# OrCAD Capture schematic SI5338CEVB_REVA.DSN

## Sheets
1 5338 main: size D; title: Si5338 Customer EVB; rev: A
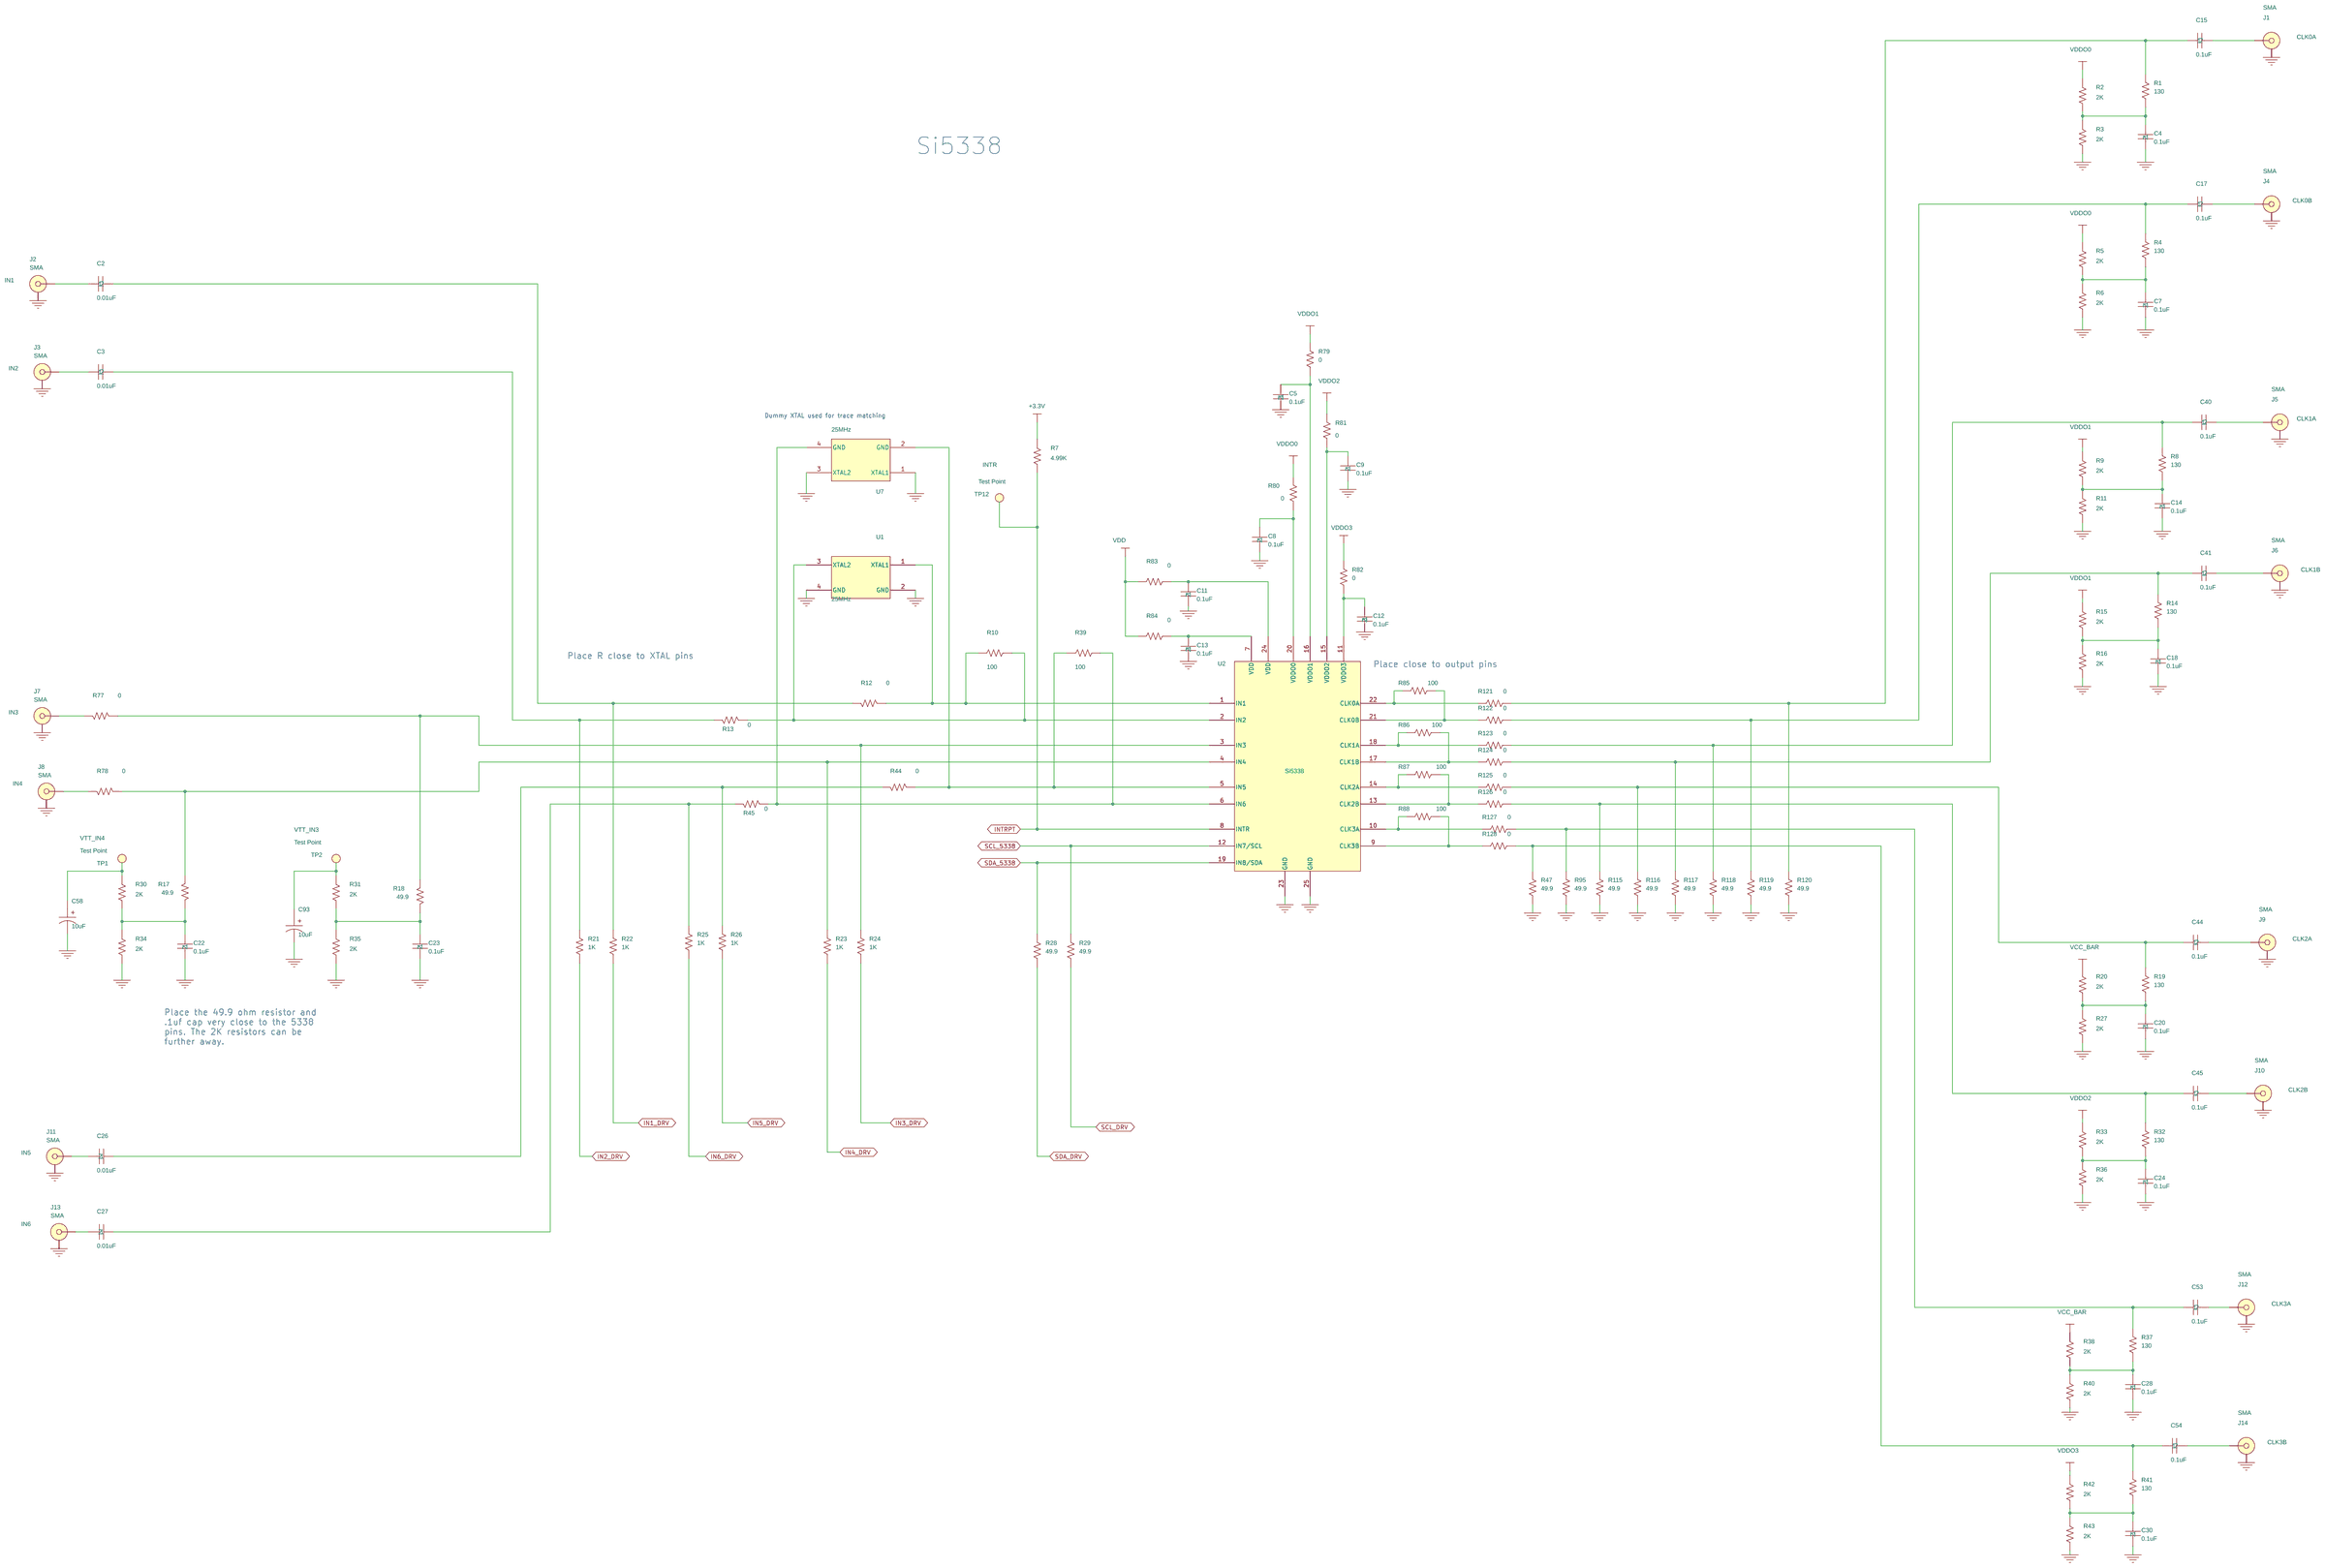
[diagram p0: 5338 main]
2 MCU: size C
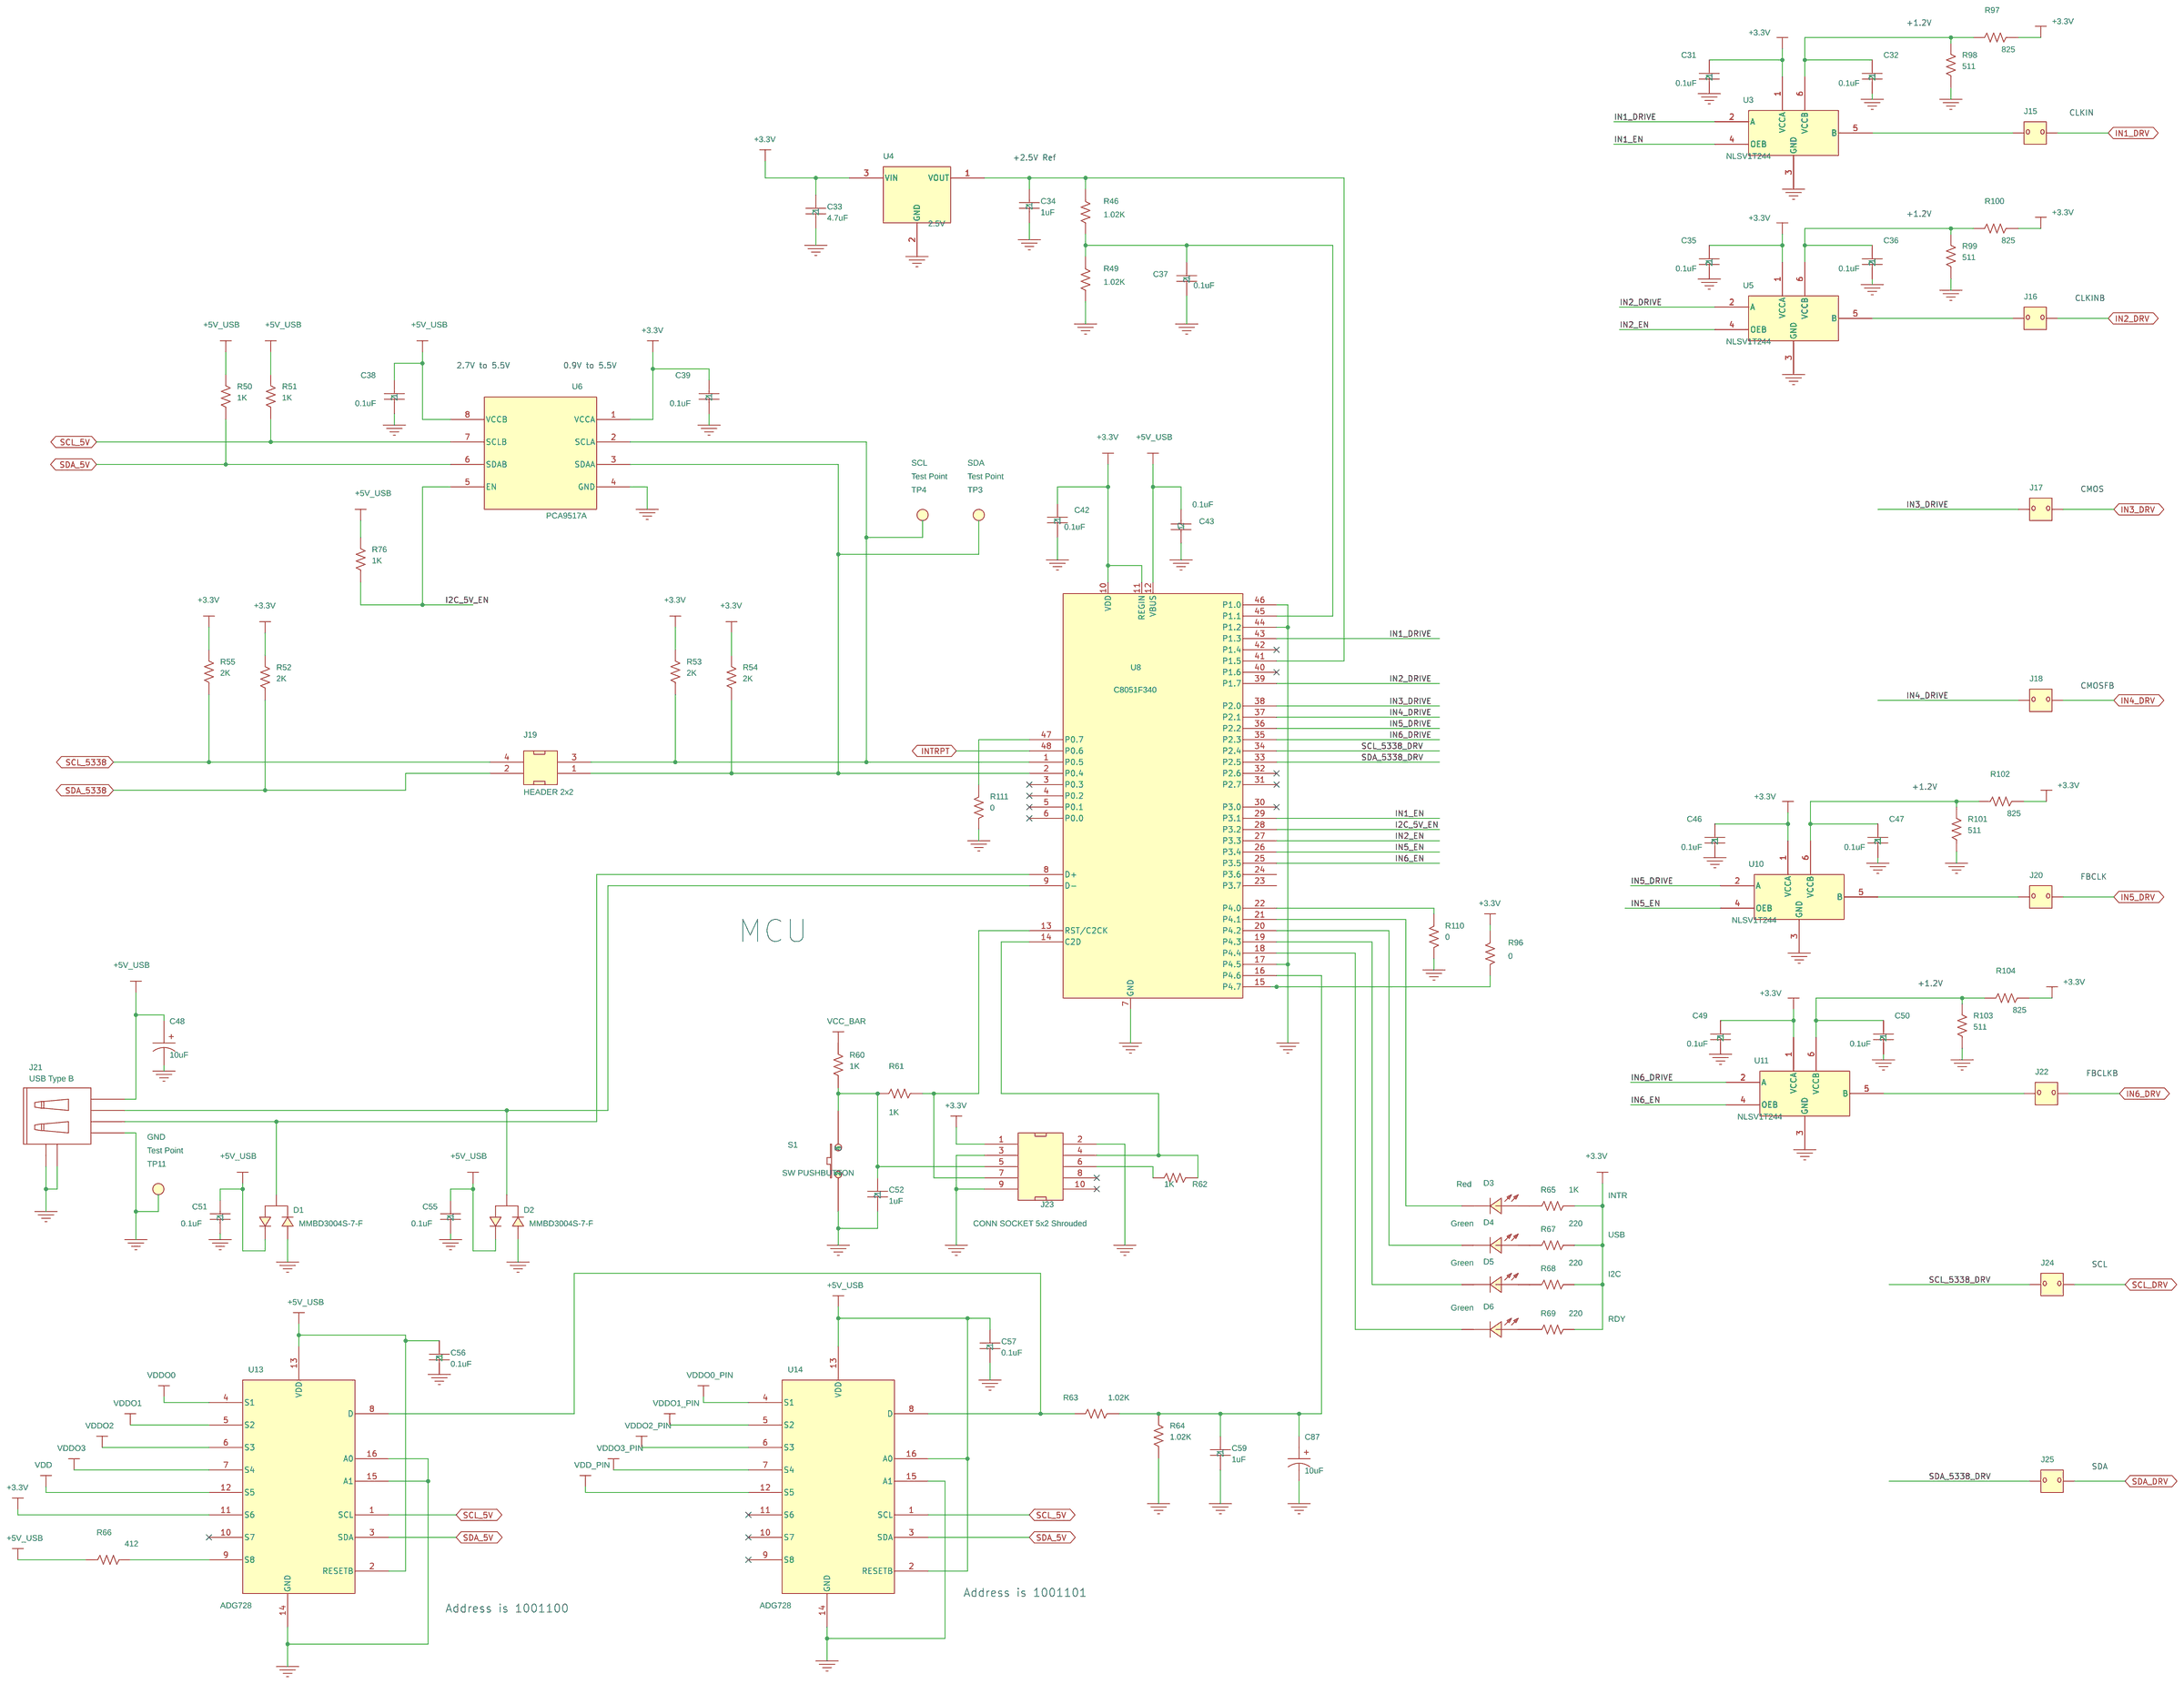
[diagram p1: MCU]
3 Voltage Regulation: size C
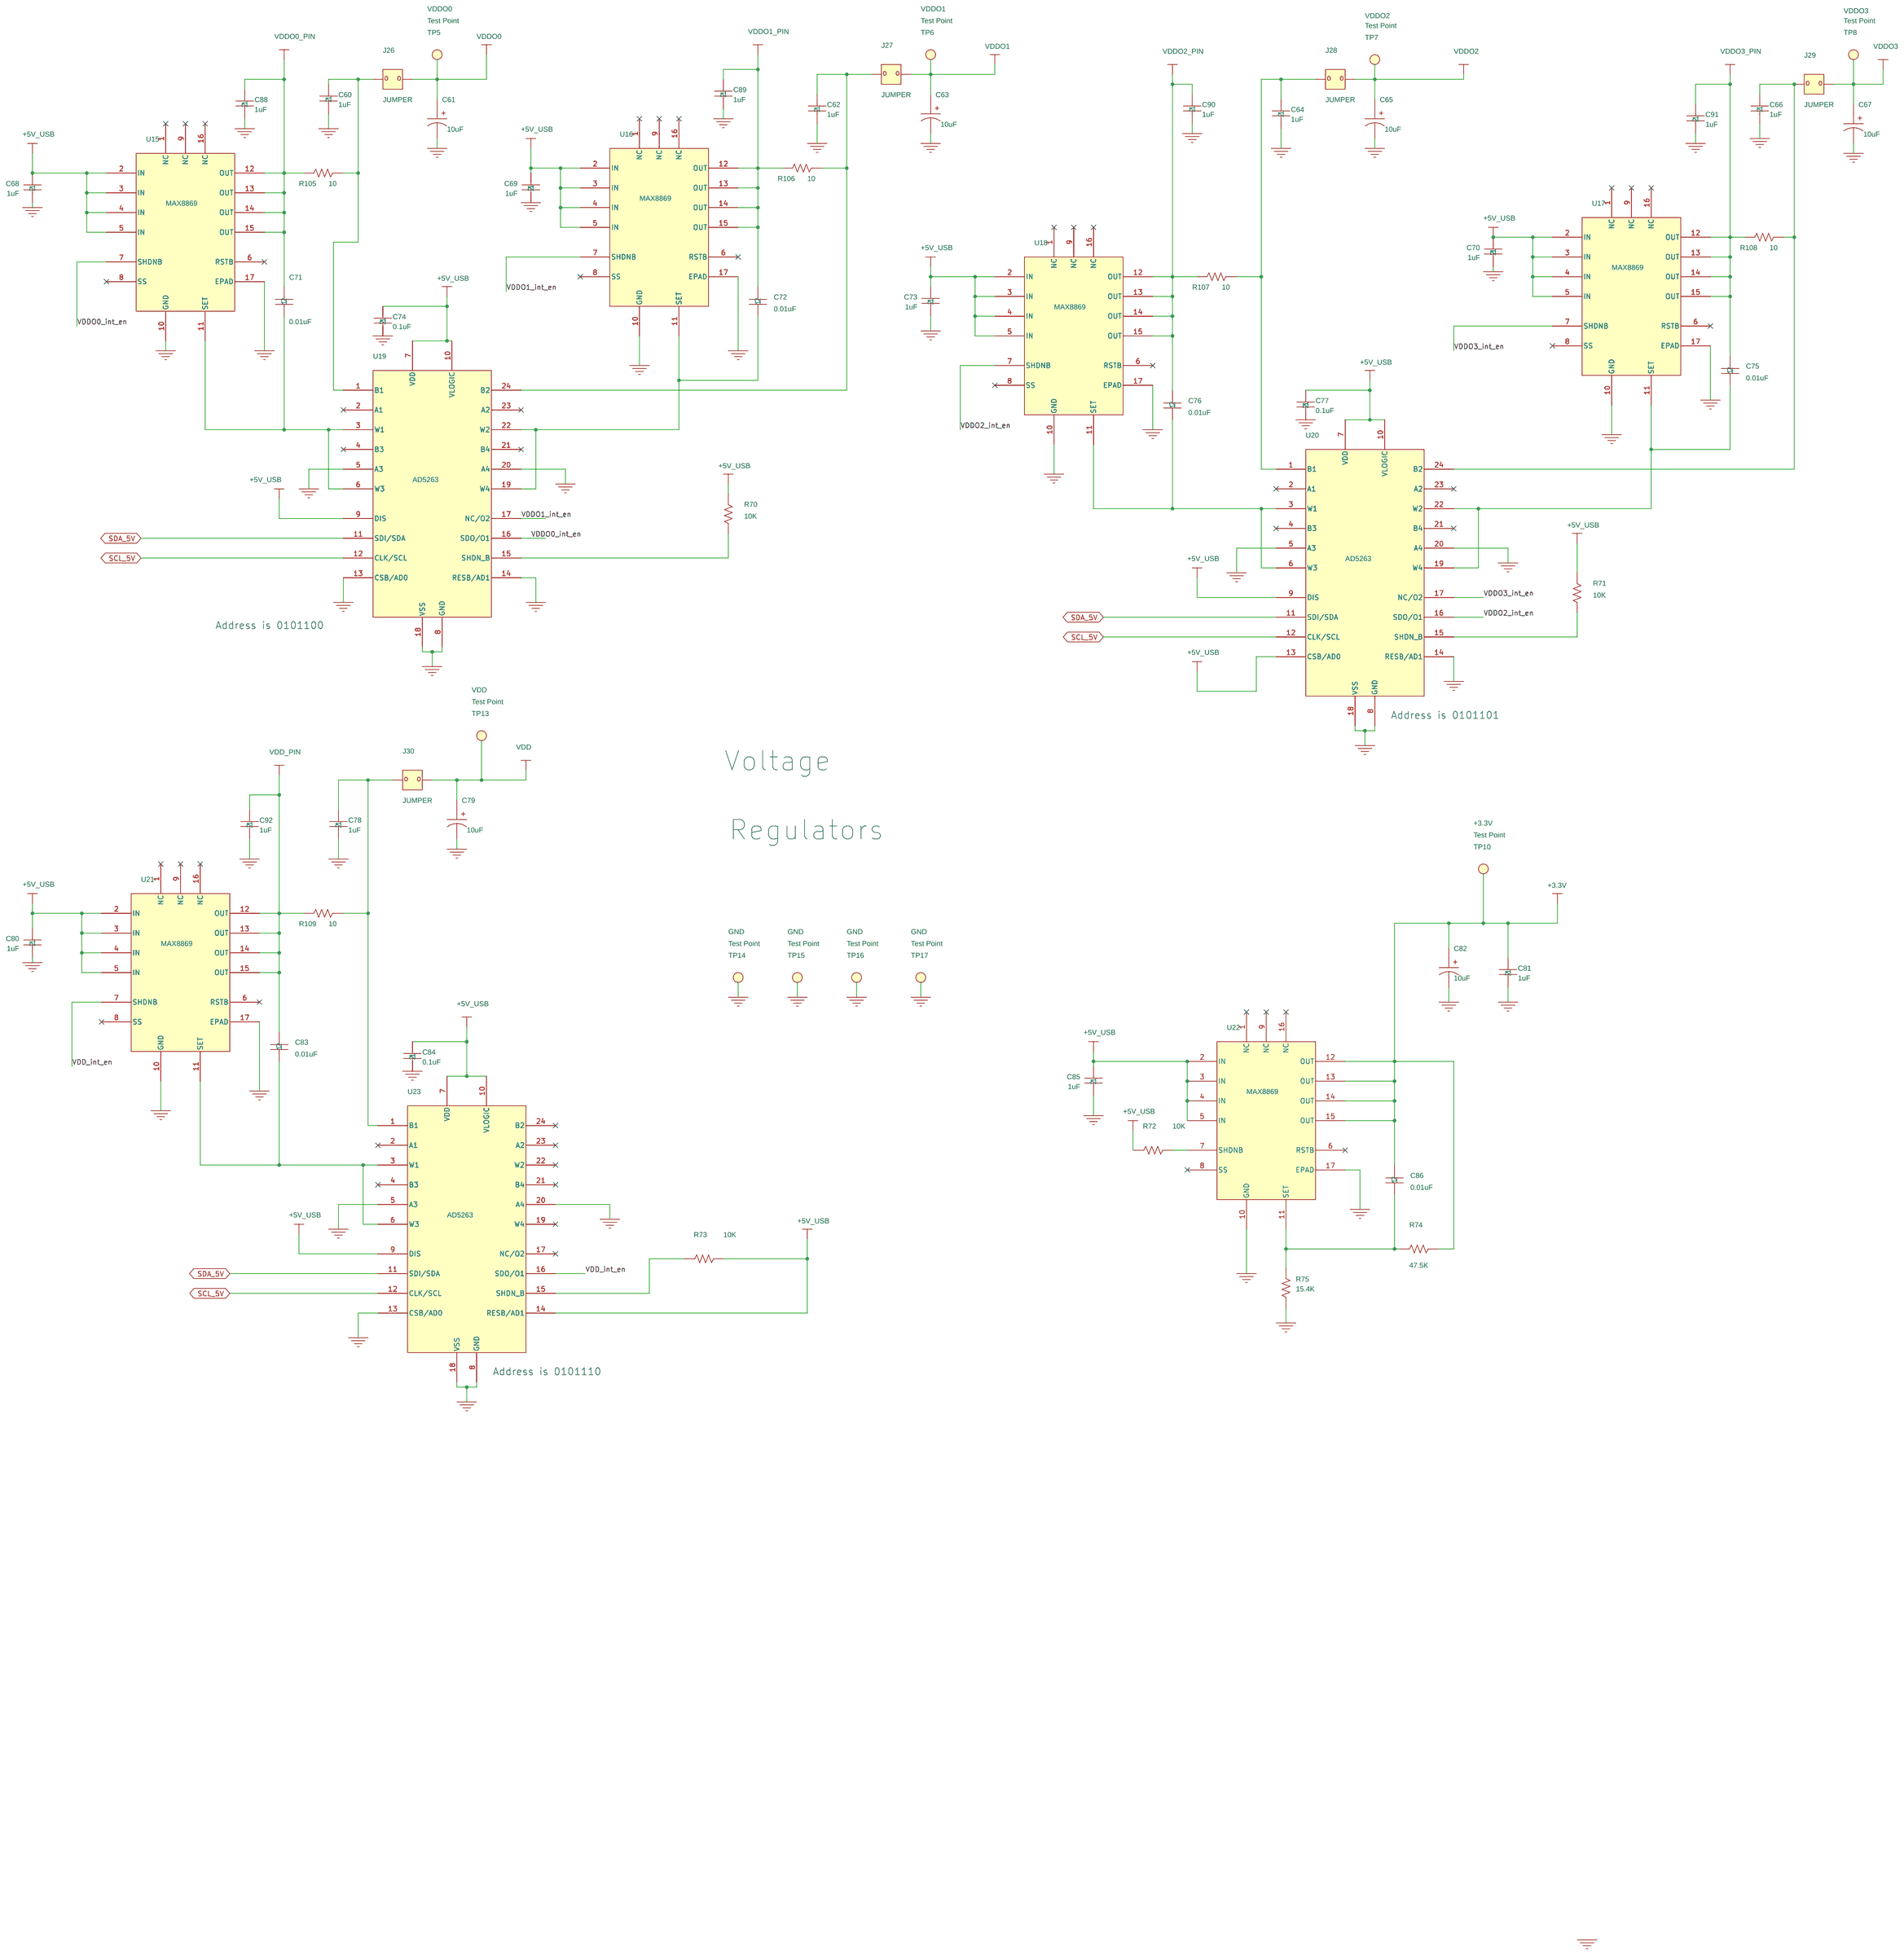
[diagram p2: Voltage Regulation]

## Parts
sheet 5338 main
C2  0.01uF  [C0402]
C3  0.01uF  [C0402]
C4  0.1uF  [C0402]
C5  0.1uF  [C0402L]
C7  0.1uF  [C0402]
C8  0.1uF  [C0402L]
C9  0.1uF  [C0402L]
C11  0.1uF  [C0402L]
C12  0.1uF  [C0402L]
C13  0.1uF  [C0402L]
C14  0.1uF  [C0402]
C15  0.1uF  [C0402]
C17  0.1uF  [C0402]
C18  0.1uF  [C0402]
C20  0.1uF  [C0402]
C22  0.1uF  [C0402L]
C23  0.1uF  [C0402L]
C24  0.1uF  [C0402]
C26  0.01uF  [C0402]
C27  0.01uF  [C0402]
C28  0.1uF  [C0402]
C30  0.1uF  [C0402]
C40  0.1uF  [C0402]
C41  0.1uF  [C0402]
C44  0.1uF  [C0402]
C45  0.1uF  [C0402]
C53  0.1uF  [C0402]
C54  0.1uF  [C0402]
C58  10uF  [6032_EIAC]
C93  10uF  [6032_EIAC]
J1  SMA  [SMA-EDGE-5]
J2  SMA  [SMA-EDGE-5]
J3  SMA  [SMA-EDGE-5]
J4  SMA  [SMA-EDGE-5]
J5  SMA  [SMA-EDGE-5]
J6  SMA  [SMA-EDGE-5]
J7  SMA  [SMA-EDGE-5]
J8  SMA  [SMA-EDGE-5]
J9  SMA  [SMA-EDGE-5]
J10  SMA  [SMA-EDGE-5]
J11  SMA  [SMA-EDGE-5]
J12  SMA  [SMA-EDGE-5]
J13  SMA  [SMA-EDGE-5]
J14  SMA  [SMA-EDGE-5]
R1  130  [R0402]
R2  2K  [R0402]
R3  2K  [R0402]
R4  130  [R0402]
R5  2K  [R0402]
R6  2K  [R0402]
R7  4.99K  [R0402]
R8  130  [R0402]
R9  2K  [R0402]
R10  100  [R0201]
R11  2K  [R0402]
R12  0  [R0402]
R13  0  [R0402]
R14  130  [R0402]
R15  2K  [R0402]
R16  2K  [R0402]
R17  49.9  [R0402L]
R18  49.9  [R0402L]
R19  130  [R0402]
R20  2K  [R0402]
R21  1K  [R0402]
R22  1K  [R0402]
R23  1K  [R0402]
R24  1K  [R0402]
R25  1K  [R0402]
R26  1K  [R0402]
R27  2K  [R0402]
R28  49.9  [R0402]
R29  49.9  [R0402]
R30  2K  [R0402]
R31  2K  [R0402]
R32  130  [R0402]
R33  2K  [R0402]
R34  2K  [R0402]
R35  2K  [R0402]
R36  2K  [R0402]
R37  130  [R0402]
R38  2K  [R0402]
R39  100  [R0201]
R40  2K  [R0402]
R41  130  [R0402]
R42  2K  [R0402]
R43  2K  [R0402]
R44  0  [R0402]
R45  0  [R0402]
R47  49.9  [R0402L]
R77  0  [R0402]
R78  0  [R0402]
R79  0  [R0603]
R80  0  [R0603]
R81  0  [R0603]
R82  0  [R0603]
R83  0  [R0603]
R84  0  [R0603]
R85  100  [R0201]
R86  100  [R0201]
R87  100  [R0201]
R88  100  [R0201]
R95  49.9  [R0402L]
R115  49.9  [R0402L]
R116  49.9  [R0402L]
R117  49.9  [R0402L]
R118  49.9  [R0402L]
R119  49.9  [R0402L]
R120  49.9  [R0402L]
R121  0  [R0201]
R122  0  [R0201]
R123  0  [R0201]
R124  0  [R0201]
R125  0  [R0201]
R126  0  [R0201]
R127  0  [R0201]
R128  0  [R0201]
TP1  Test Point  [TESTPOINT]
TP2  Test Point  [TESTPOINT]
TP12  Test Point  [TESTPOINT]
U1  25MHz  [XTAL4N-MULTI]
U2  Si5338  [QFN24N4X4P0.5]
U7  25MHz  [XTAL4N-MULTI]
sheet MCU
C31  0.1uF  [C0402]
C32  0.1uF  [C0402]
C33  4.7uF  [C1206]
C34  1uF  [C1206]
C35  0.1uF  [C0402]
C36  0.1uF  [C0402]
C37  0.1uF  [C0402]
C38  0.1uF  [C0402]
C39  0.1uF  [C0402]
C42  0.1uF  [C0402]
C43  0.1uF  [C0402]
C46  0.1uF  [C0402]
C47  0.1uF  [C0402]
C48  10uF  [6032_EIAC]
C49  0.1uF  [C0402]
C50  0.1uF  [C0402]
C51  0.1uF  [C0402]
C52  1uF  [C1206]
C55  0.1uF  [C0402]
C56  0.1uF  [C0402]
C57  0.1uF  [C0402]
C59  1uF  [C1206]
C87  10uF  [6032_EIAC]
D1  MMBD3004S-7-F  [SOT23-AKC]
D2  MMBD3004S-7-F  [SOT23-AKC]
D3  Red  [LED-S-GW-KA]
D4  Green  [LED-S-GW-AK]
D5  Green  [LED-S-GW-AK]
D6  Green  [LED-S-GW-AK]
J15  JUMPER  [CONN-1X2]
J16  JUMPER  [CONN-1X2]
J17  JUMPER  [CONN-1X2]
J18  JUMPER  [CONN-1X2]
J19  HEADER 2x2  [CONN2X2]
J20  JUMPER  [CONN-1X2]
J21  USB Type B  [CONN-USB-B]
J22  JUMPER  [CONN-1X2]
J23  CONN SOCKET 5x2 Shrouded  [CONN2X5-4W]
J24  JUMPER  [CONN-1X2]
J25  JUMPER  [CONN-1X2]
R46  1.02K  [R0402]
R49  1.02K  [R0402]
R50  1K  [R0402]
R51  1K  [R0402]
R52  2K  [R0402]
R53  2K  [R0402]
R54  2K  [R0402]
R55  2K  [R0402]
R60  1K  [R0402]
R61  1K  [R0402]
R62  1K  [R0402]
R63  1.02K  [R0402]
R64  1.02K  [R0402]
R65  1K  [R0402]
R66  412  [R0402]
R67  220  [R0402]
R68  220  [R0402]
R69  220  [R0402]
R76  1K  [R0402]
R96  0  [R0402]
R97  825  [R0603]
R98  511  [R0603]
R99  511  [R0603]
R100  825  [R0603]
R101  511  [R0603]
R102  825  [R0603]
R103  511  [R0603]
R104  825  [R0603]
R110  0  [R0402]
R111  0  [R0402]
S1  SW PUSHBUTTON  [SW-PB-MOM]
TP3  Test Point  [TESTPOINT]
TP4  Test Point  [TESTPOINT]
TP11  Test Point  [TESTPOINT]
U3  NLSV1T244  [UDFN6N1P0.4]
U4  2.5V  [SOT-23]
U5  NLSV1T244  [UDFN6N1P0.4]
U6  PCA9517A  [SO8N6.0P1.27]
U8  C8051F340  [TQFP48N9X9P0.5]
U10  NLSV1T244  [UDFN6N1P0.4]
U11  NLSV1T244  [UDFN6N1P0.4]
U13  ADG728  [TSSOP16N6.4P0.65]
U14  ADG728  [TSSOP16N6.4P0.65]
sheet Voltage Regulation
C60  1uF  [C0603]
C61  10uF  [6032_EIAC]
C62  1uF  [C0603]
C63  10uF  [6032_EIAC]
C64  1uF  [C0603]
C65  10uF  [6032_EIAC]
C66  1uF  [C0603]
C67  10uF  [6032_EIAC]
C68  1uF  [C0603]
C69  1uF  [C0603]
C70  1uF  [C0603]
C71  0.01uF  [C0402]
C72  0.01uF  [C0402]
C73  1uF  [C0603]
C74  0.1uF  [C0402]
C75  0.01uF  [C0402]
C76  0.01uF  [C0402]
C77  0.1uF  [C0402]
C78  1uF  [C0603]
C79  10uF  [6032_EIAC]
C80  1uF  [C0603]
C81  1uF  [C0603]
C82  10uF  [6032_EIAC]
C83  0.01uF  [C0402]
C84  0.1uF  [C0402]
C85  1uF  [C0603]
C86  0.01uF  [C0402]
C88  1uF  [C0603]
C89  1uF  [C0603]
C90  1uF  [C0603]
C91  1uF  [C0603]
C92  1uF  [C0603]
J26  JUMPER  [CONN-1X2]
J27  JUMPER  [CONN-1X2]
J28  JUMPER  [CONN-1X2]
J29  JUMPER  [CONN-1X2]
J30  JUMPER  [CONN-1X2]
R70  10K  [R0402]
R71  10K  [R0402]
R72  10K  [R0402]
R73  10K  [R0402]
R74  47.5K  [R0603]
R75  15.4K  [R0603]
R105  10  [R2512]
R106  10  [R2512]
R107  10  [R2512]
R108  10  [R2512]
R109  10  [R2512]
TP5  Test Point  [TESTPOINT]
TP6  Test Point  [TESTPOINT]
TP7  Test Point  [TESTPOINT]
TP8  Test Point  [TESTPOINT]
TP10  Test Point  [TESTPOINT]
TP13  Test Point  [TESTPOINT]
TP14  Test Point  [TESTPOINT]
TP15  Test Point  [TESTPOINT]
TP16  Test Point  [TESTPOINT]
TP17  Test Point  [TESTPOINT]
U15  MAX8869  [TSSOP16N6.5P0.65E]
U16  MAX8869  [TSSOP16N6.5P0.65E]
U17  MAX8869  [TSSOP16N6.5P0.65E]
U18  MAX8869  [TSSOP16N6.5P0.65E]
U19  AD5263  [TSSOP24N6.4P0.65]
U20  AD5263  [TSSOP24N6.4P0.65]
U21  MAX8869  [TSSOP16N6.5P0.65E]
U22  MAX8869  [TSSOP16N6.5P0.65E]
U23  AD5263  [TSSOP24N6.4P0.65]

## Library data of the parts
C2 = CAP_NP_27: CAP, 0.01uF, 10V, ±20%, X7R, 0402; Manufacturer: Venkel; ManufacturerPN: C0402X7R100-103M; Part_Type: CAP/NP; SiLabsPN: C0402X7R100-103M; Tolerance: ±20%; Type: X7R; Voltage: 10V; Datasheet: PID_C.pdf
C3 C71 = CAP_NP_18: CAP, 0.01uF, 10V, ±20%, X7R, 0402; Manufacturer: Venkel; ManufacturerPN: C0402X7R100-103M; Part_Type: CAP/NP; SiLabsPN: C0402X7R100-103M; Tolerance: ±20%; Type: X7R; Voltage: 10V; Datasheet: PID_C.pdf
C4 C50 = CAP_NP_5: CAP, 0.1uF, 10V, ±10%, X7R, 0402; Manufacturer: Venkel; ManufacturerPN: C0402X7R100-104K; Part_Type: CAP/NP; SiLabsPN: C0402X7R100-104K; Tolerance: ±10%; Type: X7R; Voltage: 10V; Datasheet: PID_C.pdf
C5 = CAP_NP_7: CAP, 0.1uF, 10V, ±10%, X7R, 0402; Manufacturer: Venkel; ManufacturerPN: C0402X7R100-104K; Part_Type: CAP/NP; SiLabsPN: C0402X7R100-104K; Tolerance: ±10%; Type: X7R; Voltage: 10V; Datasheet: PID_C.pdf
C7 C42 = CAP_NP_3: CAP, 0.1uF, 10V, ±10%, X7R, 0402; Manufacturer: Venkel; ManufacturerPN: C0402X7R100-104K; Part_Type: CAP/NP; SiLabsPN: C0402X7R100-104K; Tolerance: ±10%; Type: X7R; Voltage: 10V; Datasheet: PID_C.pdf
C8 C47 C84 = CAP_NP: CAP, 0.1uF, 10V, ±10%, X7R, 0402; Manufacturer: Venkel; ManufacturerPN: C0402X7R100-104K; Part_Type: CAP/NP; SiLabsPN: C0402X7R100-104K; Tolerance: ±10%; Type: X7R; Voltage: 10V; Datasheet: PID_C.pdf
C9 C56 = CAP_NP_9: CAP, 0.1uF, 10V, ±10%, X7R, 0402; Manufacturer: Venkel; ManufacturerPN: C0402X7R100-104K; Part_Type: CAP/NP; SiLabsPN: C0402X7R100-104K; Tolerance: ±10%; Type: X7R; Voltage: 10V; Datasheet: PID_C.pdf
C11 C57 = CAP_NP_14: CAP, 0.1uF, 10V, ±10%, X7R, 0402; Manufacturer: Venkel; ManufacturerPN: C0402X7R100-104K; Part_Type: CAP/NP; SiLabsPN: C0402X7R100-104K; Tolerance: ±10%; Type: X7R; Voltage: 10V; Datasheet: PID_C.pdf
C12 C37 = CAP_NP_13: CAP, 0.1uF, 10V, ±10%, X7R, 0402; Manufacturer: Venkel; ManufacturerPN: C0402X7R100-104K; Part_Type: CAP/NP; SiLabsPN: C0402X7R100-104K; Tolerance: ±10%; Type: X7R; Voltage: 10V; Datasheet: PID_C.pdf
C13 C39 = CAP_NP_20: CAP, 0.1uF, 10V, ±10%, X7R, 0402; Manufacturer: Venkel; ManufacturerPN: C0402X7R100-104K; Part_Type: CAP/NP; SiLabsPN: C0402X7R100-104K; Tolerance: ±10%; Type: X7R; Voltage: 10V; Datasheet: PID_C.pdf
C14 = CAP_NP_11: CAP, 0.1uF, 10V, ±10%, X7R, 0402; Manufacturer: Venkel; ManufacturerPN: C0402X7R100-104K; Part_Type: CAP/NP; SiLabsPN: C0402X7R100-104K; Tolerance: ±10%; Type: X7R; Voltage: 10V; Datasheet: PID_C.pdf
C15 C43 = CAP_NP_4: CAP, 0.1uF, 10V, ±10%, X7R, 0402; Manufacturer: Venkel; ManufacturerPN: C0402X7R100-104K; Part_Type: CAP/NP; SiLabsPN: C0402X7R100-104K; Tolerance: ±10%; Type: X7R; Voltage: 10V; Datasheet: PID_C.pdf
C17 C74 = CAP_NP_22: CAP, 0.1uF, 10V, ±10%, X7R, 0402; Manufacturer: Venkel; ManufacturerPN: C0402X7R100-104K; Part_Type: CAP/NP; SiLabsPN: C0402X7R100-104K; Tolerance: ±10%; Type: X7R; Voltage: 10V; Datasheet: PID_C.pdf
C18 C38 = CAP_NP_8: CAP, 0.1uF, 10V, ±10%, X7R, 0402; Manufacturer: Venkel; ManufacturerPN: C0402X7R100-104K; Part_Type: CAP/NP; SiLabsPN: C0402X7R100-104K; Tolerance: ±10%; Type: X7R; Voltage: 10V; Datasheet: PID_C.pdf
C20 = CAP_NP_25: CAP, 0.1uF, 10V, ±10%, X7R, 0402; Manufacturer: Venkel; ManufacturerPN: C0402X7R100-104K; Part_Type: CAP/NP; SiLabsPN: C0402X7R100-104K; Tolerance: ±10%; Type: X7R; Voltage: 10V; Datasheet: PID_C.pdf
C22 C49 = CAP_NP_2: CAP, 0.1uF, 10V, ±10%, X7R, 0402; Manufacturer: Venkel; ManufacturerPN: C0402X7R100-104K; Part_Type: CAP/NP; SiLabsPN: C0402X7R100-104K; Tolerance: ±10%; Type: X7R; Voltage: 10V; Datasheet: PID_C.pdf
C23 = CAP_NP_26: CAP, 0.1uF, 10V, ±10%, X7R, 0402; Manufacturer: Venkel; ManufacturerPN: C0402X7R100-104K; Part_Type: CAP/NP; SiLabsPN: C0402X7R100-104K; Tolerance: ±10%; Type: X7R; Voltage: 10V; Datasheet: PID_C.pdf
C24 = CAP_NP_19: CAP, 0.1uF, 10V, ±10%, X7R, 0402; Manufacturer: Venkel; ManufacturerPN: C0402X7R100-104K; Part_Type: CAP/NP; SiLabsPN: C0402X7R100-104K; Tolerance: ±10%; Type: X7R; Voltage: 10V; Datasheet: PID_C.pdf
C26 C76 = CAP_NP_21: CAP, 0.01uF, 10V, ±20%, X7R, 0402; Manufacturer: Venkel; ManufacturerPN: C0402X7R100-103M; Part_Type: CAP/NP; SiLabsPN: C0402X7R100-103M; Tolerance: ±20%; Type: X7R; Voltage: 10V; Datasheet: PID_C.pdf
C27 = CAP_NP_24: CAP, 0.01uF, 10V, ±20%, X7R, 0402; Manufacturer: Venkel; ManufacturerPN: C0402X7R100-103M; Part_Type: CAP/NP; SiLabsPN: C0402X7R100-103M; Tolerance: ±20%; Type: X7R; Voltage: 10V; Datasheet: PID_C.pdf
C28 C31 = CAP_NP_15: CAP, 0.1uF, 10V, ±10%, X7R, 0402; Manufacturer: Venkel; ManufacturerPN: C0402X7R100-104K; Part_Type: CAP/NP; SiLabsPN: C0402X7R100-104K; Tolerance: ±10%; Type: X7R; Voltage: 10V; Datasheet: PID_C.pdf
C30 C55 = CAP_NP_6: CAP, 0.1uF, 10V, ±10%, X7R, 0402; Manufacturer: Venkel; ManufacturerPN: C0402X7R100-104K; Part_Type: CAP/NP; SiLabsPN: C0402X7R100-104K; Tolerance: ±10%; Type: X7R; Voltage: 10V; Datasheet: PID_C.pdf
C32 C40 = CAP_NP_16: CAP, 0.1uF, 10V, ±10%, X7R, 0402; Manufacturer: Venkel; ManufacturerPN: C0402X7R100-104K; Part_Type: CAP/NP; SiLabsPN: C0402X7R100-104K; Tolerance: ±10%; Type: X7R; Voltage: 10V; Datasheet: PID_C.pdf
C35 C41 = CAP_NP_10: CAP, 0.1uF, 10V, ±10%, X7R, 0402; Manufacturer: Venkel; ManufacturerPN: C0402X7R100-104K; Part_Type: CAP/NP; SiLabsPN: C0402X7R100-104K; Tolerance: ±10%; Type: X7R; Voltage: 10V; Datasheet: PID_C.pdf
C44 C51 = CAP_NP_1: CAP, 0.1uF, 10V, ±10%, X7R, 0402; Manufacturer: Venkel; ManufacturerPN: C0402X7R100-104K; Part_Type: CAP/NP; SiLabsPN: C0402X7R100-104K; Tolerance: ±10%; Type: X7R; Voltage: 10V; Datasheet: PID_C.pdf
C45 = CAP_NP_23: CAP, 0.1uF, 10V, ±10%, X7R, 0402; Manufacturer: Venkel; ManufacturerPN: C0402X7R100-104K; Part_Type: CAP/NP; SiLabsPN: C0402X7R100-104K; Tolerance: ±10%; Type: X7R; Voltage: 10V; Datasheet: PID_C.pdf
C36 C53 = CAP_NP_17: CAP, 0.1uF, 10V, ±10%, X7R, 0402; Manufacturer: Venkel; ManufacturerPN: C0402X7R100-104K; Part_Type: CAP/NP; SiLabsPN: C0402X7R100-104K; Tolerance: ±10%; Type: X7R; Voltage: 10V; Datasheet: PID_C.pdf
C54 = CAP_NP_12: CAP, 0.1uF, 10V, ±10%, X7R, 0402; Manufacturer: Venkel; ManufacturerPN: C0402X7R100-104K; Part_Type: CAP/NP; SiLabsPN: C0402X7R100-104K; Tolerance: ±10%; Type: X7R; Voltage: 10V; Datasheet: PID_C.pdf
C48 C58 C61 C63 C65 C67 C79 C82 C87 C93 = CAP_POL: CAP, 10uF, 25V, ±20%, TANT, 6032-28; Manufacturer: Kemet; ManufacturerPN: B45196H5106M309; Part_Type: CAP/POL; SiLabsPN: B45196H5106M309; Tolerance: ±20%; Type: TANT; Voltage: 25V; Datasheet: B45196E_High_Cap.pdf
J1 = COAX_5PIN: SMA, 50 Ohm, End Launch Jack Receptacle - Round Contact, Edge Mount; Manufacturer: Johnson Components; ManufacturerPN: 142-0701-801; Part_Type: CON; SiLabsPN: 142-0701-801; Silk: CLK0A; Type: RF; Datasheet: 1420701801.pdf
J2 = COAX_5PIN: SMA, 50 Ohm, End Launch Jack Receptacle - Round Contact, Edge Mount; Manufacturer: Johnson Components; ManufacturerPN: 142-0701-801; Part_Type: CON; SiLabsPN: 142-0701-801; Silk: IN1; Type: RF; Datasheet: 1420701801.pdf
J3 = COAX_5PIN: SMA, 50 Ohm, End Launch Jack Receptacle - Round Contact, Edge Mount; Manufacturer: Johnson Components; ManufacturerPN: 142-0701-801; Part_Type: CON; SiLabsPN: 142-0701-801; Silk: IN2; Type: RF; Datasheet: 1420701801.pdf
J4 = COAX_5PIN: SMA, 50 Ohm, End Launch Jack Receptacle - Round Contact, Edge Mount; Manufacturer: Johnson Components; ManufacturerPN: 142-0701-801; Part_Type: CON; SiLabsPN: 142-0701-801; Silk: CLK0B; Type: RF; Datasheet: 1420701801.pdf
J5 = COAX_5PIN: SMA, 50 Ohm, End Launch Jack Receptacle - Round Contact, Edge Mount; Manufacturer: Johnson Components; ManufacturerPN: 142-0701-801; Part_Type: CON; SiLabsPN: 142-0701-801; Silk: CLK1A; Type: RF; Datasheet: 1420701801.pdf
J6 = COAX_5PIN: SMA, 50 Ohm, End Launch Jack Receptacle - Round Contact, Edge Mount; Manufacturer: Johnson Components; ManufacturerPN: 142-0701-801; Part_Type: CON; SiLabsPN: 142-0701-801; Silk: CLK1B; Type: RF; Datasheet: 1420701801.pdf
J7 = COAX_5PIN: SMA, 50 Ohm, End Launch Jack Receptacle - Round Contact, Edge Mount; Manufacturer: Johnson Components; ManufacturerPN: 142-0701-801; Part_Type: CON; SiLabsPN: 142-0701-801; Silk: IN3; Type: RF; Datasheet: 1420701801.pdf
J8 = COAX_5PIN: SMA, 50 Ohm, End Launch Jack Receptacle - Round Contact, Edge Mount; Manufacturer: Johnson Components; ManufacturerPN: 142-0701-801; Part_Type: CON; SiLabsPN: 142-0701-801; Silk: IN4; Type: RF; Datasheet: 1420701801.pdf
J9 = COAX_5PIN: SMA, 50 Ohm, End Launch Jack Receptacle - Round Contact, Edge Mount; Manufacturer: Johnson Components; ManufacturerPN: 142-0701-801; Part_Type: CON; SiLabsPN: 142-0701-801; Silk: CLK2A; Type: RF; Datasheet: 1420701801.pdf
J10 = COAX_5PIN: SMA, 50 Ohm, End Launch Jack Receptacle - Round Contact, Edge Mount; Manufacturer: Johnson Components; ManufacturerPN: 142-0701-801; Part_Type: CON; SiLabsPN: 142-0701-801; Silk: CLK2B; Type: RF; Datasheet: 1420701801.pdf
J11 = COAX_5PIN: SMA, 50 Ohm, End Launch Jack Receptacle - Round Contact, Edge Mount; Manufacturer: Johnson Components; ManufacturerPN: 142-0701-801; Part_Type: CON; SiLabsPN: 142-0701-801; Silk: IN5; Type: RF; Datasheet: 1420701801.pdf
J12 = COAX_5PIN: SMA, 50 Ohm, End Launch Jack Receptacle - Round Contact, Edge Mount; Manufacturer: Johnson Components; ManufacturerPN: 142-0701-801; Part_Type: CON; SiLabsPN: 142-0701-801; Silk: CLK3A; Type: RF; Datasheet: 1420701801.pdf
J13 = COAX_5PIN: SMA, 50 Ohm, End Launch Jack Receptacle - Round Contact, Edge Mount; Manufacturer: Johnson Components; ManufacturerPN: 142-0701-801; Part_Type: CON; SiLabsPN: 142-0701-801; Silk: IN6; Type: RF; Datasheet: 1420701801.pdf
J14 = COAX_5PIN: SMA, 50 Ohm, End Launch Jack Receptacle - Round Contact, Edge Mount; Manufacturer: Johnson Components; ManufacturerPN: 142-0701-801; Part_Type: CON; SiLabsPN: 142-0701-801; Silk: CLK3B; Type: RF; Datasheet: 1420701801.pdf
R1 R4 R8 R14 R19 R32 R37 R41 = RES_V: RES, 130 Ohm, 1/16W, ±5%, ThickFilm, 0402; Manufacturer: Venkel; ManufacturerPN: CR0402-16W-131F; Part_Type: RES/SMT; Rating: 1/16W; SiLabsPN: CR0402-16W-131F; Tolerance: ±1%; Type: ThickFilm; Datasheet: PID_CR.pdf
R2 R3 R5 R6 R9 R11 R15 R16 R20 R27 R30 R31 R33-R36 R38 R40 R42 R43 = RES_V: RES, 2K, 1/16W, ±25PPM, ±0.1%, ThinFilm, 0402; Manufacturer: Venkel; ManufacturerPN: TFCR0402-16W-E-2001B; Part_Type: RES/SMT; Rating: 1/16W; SiLabsPN: TFCR0402-16W-E-2001B; Tolerance: ±0.1%; Type: ThinFilm; Datasheet: PID_TFCR.pdf
R7 = RES_V: RES, 4.99K, 1/16W, ±1%, ThickFilm, 0402; Manufacturer: Venkel; ManufacturerPN: CR0402-16W-4991F; Part_Type: RES/SMT; Rating: 1/16W; SiLabsPN: CR0402-16W-4991F; Tolerance: ±1%; Type: ThickFilm; Datasheet: PID_CR.pdf
R10 R39 R85-R88 = RES_V: RES, 100 Ohm, 1/20W, ±1%, ThickFilm, 0201; Manufacturer: Venkel; ManufacturerPN: CR0201-20W-1000F; Part_Type: RES/SMT; Rating: 1/20W; SiLabsPN: CR0201-20W-1000F; Tolerance: ±1%; Type: ThickFilm; Datasheet: PID_CR.pdf
R12 R13 R44 R45 R77 R78 R96 R110 R111 = RES_V: RES, 0 Ohm, 1A, ThickFilm, 0402; Manufacturer: Venkel; ManufacturerPN: CR0402-16W-000; Part_Type: RES/SMT; Rating: 1A; SiLabsPN: CR0402-16W-000; Type: ThickFilm; Datasheet: PID_CR.pdf
R17 R18 R28 R29 R47 R95 R115-R120 = RES_V: RES, 49.9 Ohm, 1/16W, ±1%, ThickFilm, 0402; Manufacturer: Venkel; ManufacturerPN: CR0402-16W-49R9F; Part_Type: RES/SMT; Rating: 1/16W; SiLabsPN: CR0402-16W-49R9F; Tolerance: ±1%; Type: ThickFilm; Datasheet: PID_CR.pdf
R21-R26 R50 R51 R60-R62 R65 R76 = RES_V: RES, 1K, 1/16W, ±5%, ThickFilm, 0402; Manufacturer: Venkel; ManufacturerPN: CR0402-16W-102J; Part_Type: RES/SMT; Rating: 1/16W; SiLabsPN: CR0402-16W-102J; Tolerance: ±5%; Type: ThickFilm; Datasheet: PID_CR.pdf
R79-R84 = RES_V: RES, 0 Ohm, 1A, ThickFilm, 0603; Manufacturer: Venkel; ManufacturerPN: CR0603-16W-000; Part_Type: RES/SMT; Rating: 1A; SiLabsPN: CR0603-16W-000; Type: ThickFilm; Datasheet: PID_CR.pdf
R121-R128 = RES_V: RES, 0 Ohm, 1/20W, ±1%, ThickFilm, 0201; Manufacturer: Venkel; ManufacturerPN: CR0201-20W-000F; Part_Type: RES/SMT; Rating: 1/20W; SiLabsPN: TMP-600; Tolerance: ±1%; Type: ThickFilm; Datasheet: PID_CR.pdf
TP1 = TEST_POINT: TH Red TESTPOINT; Manufacturer: Kobiconn; ManufacturerPN: 151-207; SiLabsPN: 151-207; Silk: VTT_IN4; Type: Red
TP2 = TEST_POINT: TH Red TESTPOINT; Manufacturer: Kobiconn; ManufacturerPN: 151-207; SiLabsPN: 151-207; Silk: VTT_IN3; Type: Red
TP12 = TEST_POINT: TH Red TESTPOINT; Manufacturer: Kobiconn; ManufacturerPN: 151-207; SiLabsPN: 151-207; Silk: INTR; Type: Red
U1 U7 = FA-238: XTAL 25MHz, 3.2MM X 2.5MM, LOW PROFILE SMD; Manufacturer: Epson; ManufacturerPN: FA-238 25.0000MB; Part_Type: IC; SiLabsPN: FA-238 25.0000MB; Datasheet: FA-238.pdf
U2 = Si5338: Programmable Four Frequency Clock Multiplier; Manufacturer: SiLabs; Part_Type: IC/SILABS; Type: Timing
C33 = CAP_NP_19: CAP, 4.7uF, 10V, ±20%, X7R, 1206; Manufacturer: Venkel; ManufacturerPN: C1206X7R100-475M; Part_Type: CAP/NP; SiLabsPN: C1206X7R100-475M; Tolerance: ±20%; Type: X7R; Voltage: 10V; Datasheet: PID_C.pdf
C34 = CAP_NP_7: CAP, 1uF, 25V, ±10%, X7R, 1206; Manufacturer: Venkel; ManufacturerPN: C1206X7R250-105K; Part_Type: CAP/NP; SiLabsPN: C1206X7R250-105K; Tolerance: ±10%; Type: X7R; Voltage: 25V; Datasheet: PID_C.pdf
C46 = CAP_NP_18: CAP, 0.1uF, 10V, ±10%, X7R, 0402; Manufacturer: Venkel; ManufacturerPN: C0402X7R100-104K; Part_Type: CAP/NP; SiLabsPN: C0402X7R100-104K; Tolerance: ±10%; Type: X7R; Voltage: 10V; Datasheet: PID_C.pdf
C52 = CAP_NP_12: CAP, 1uF, 25V, ±10%, X7R, 1206; Manufacturer: Venkel; ManufacturerPN: C1206X7R250-105K; Part_Type: CAP/NP; SiLabsPN: C1206X7R250-105K; Tolerance: ±10%; Type: X7R; Voltage: 25V; Datasheet: PID_C.pdf
C59 = CAP_NP_11: CAP, 1uF, 25V, ±10%, X7R, 1206; Manufacturer: Venkel; ManufacturerPN: C1206X7R250-105K; Part_Type: CAP/NP; SiLabsPN: C1206X7R250-105K; Tolerance: ±10%; Type: X7R; Voltage: 25V; Datasheet: PID_C.pdf
D1 D2 = DIODE_DUAL_SERIES: DIO, DUAL, Switching; Manufacturer: Diodes Inc.; Part_Type: DIO/SMT; Rating: 430mA; Type: DUAL; Voltage: 300V; Datasheet: ds30353.pdf
D3 = LED: LED, Red; Manufacturer: Panasonic; ManufacturerPN: LN1271RAL; Part_Type: DIO/SMT; SiLabsPN: LN1271RAL; Silk: INTR; Datasheet: LN1371G and LN1271RAL.pdf
D4 = LED: LED, Green; Manufacturer: Panasonic; ManufacturerPN: LN1371G; Part_Type: DIO/SMT; SiLabsPN: LN1371G; Silk: USB; Datasheet: LN1371G and LN1271RAL.pdf
D5 = LED: LED, Green; Manufacturer: Panasonic; ManufacturerPN: LN1371G; Part_Type: DIO/SMT; SiLabsPN: LN1371G; Silk: I2C; Datasheet: LN1371G and LN1271RAL.pdf
D6 = LED: LED, Green; Manufacturer: Panasonic; ManufacturerPN: LN1371G; Part_Type: DIO/SMT; SiLabsPN: LN1371G; Silk: RDY; Datasheet: LN1371G and LN1271RAL.pdf
J15 = JUMPER: 2x1, 0.1in pitch, Tin Plated; Manufacturer: Samtec; ManufacturerPN: TSW-102-07-T-S; Part_Type: CON/HEADER; SiLabsPN: TSW-102-07-T-S; Silk: IN1_CNTRL; Type: Unshrouded; Datasheet: TSW_TH.pdf
J16 = JUMPER: 2x1, 0.1in pitch, Tin Plated; Manufacturer: Samtec; ManufacturerPN: TSW-102-07-T-S; Part_Type: CON/HEADER; SiLabsPN: TSW-102-07-T-S; Silk: IN2_CNTRL; Type: Unshrouded; Datasheet: TSW_TH.pdf
J17 = JUMPER: 2x1, 0.1in pitch, Tin Plated; Manufacturer: Samtec; ManufacturerPN: TSW-102-07-T-S; Part_Type: CON/HEADER; SiLabsPN: TSW-102-07-T-S; Silk: IN3_CNTRL; Type: Unshrouded; Datasheet: TSW_TH.pdf
J18 = JUMPER: 2x1, 0.1in pitch, Tin Plated; Manufacturer: Samtec; ManufacturerPN: TSW-102-07-T-S; Part_Type: CON/HEADER; SiLabsPN: TSW-102-07-T-S; Silk: IN4_CNTRL; Type: Unshrouded; Datasheet: TSW_TH.pdf
J19 = CONN_2x2: 2x2, 0.1in pitch, Tin Plated; Manufacturer: Samtec; ManufacturerPN: TSW-102-07-T-D; Part_Type: CON/HEADER; SiLabsPN: TSW-102-07-T-D; Type: Header; Datasheet: TSW_TH.PDF
J20 = JUMPER: 2x1, 0.1in pitch, Tin Plated; Manufacturer: Samtec; ManufacturerPN: TSW-102-07-T-S; Part_Type: CON/HEADER; SiLabsPN: TSW-102-07-T-S; Silk: IN5_CNTRL; Type: Unshrouded; Datasheet: TSW_TH.pdf
J21 = CN-USB: USB Type B Right Angle Connector; Manufacturer: Tyco; ManufacturerPN: 292304-1; Part_Type: CON; SiLabsPN: 292304-1; Type: USB; Datasheet: ENG_DS_7-1773442-0_0306.pdf
J22 = JUMPER: 2x1, 0.1in pitch, Tin Plated; Manufacturer: Samtec; ManufacturerPN: TSW-102-07-T-S; Part_Type: CON/HEADER; SiLabsPN: TSW-102-07-T-S; Silk: IN6_CNTRL; Type: Unshrouded; Datasheet: TSW_TH.pdf
J23 = CONN_5x2: 5x2, 0.1in pitch, Shrouded Surface mount; Manufacturer: Samtec; ManufacturerPN: HTST-105-01-LM-DV-A; Part_Type: CON/HEADER; SiLabsPN: HTST-105-01-LM-DV-A; Type: Socket; Datasheet: HTST-1XX-01-XX-D-XX-XX-MKT.pdf
J24 = JUMPER: 2x1, 0.1in pitch, Tin Plated; Manufacturer: Samtec; ManufacturerPN: TSW-102-07-T-S; Part_Type: CON/HEADER; SiLabsPN: TSW-102-07-T-S; Silk: IN7/SCL; Type: Unshrouded; Datasheet: TSW_TH.pdf
J25 = JUMPER: 2x1, 0.1in pitch, Tin Plated; Manufacturer: Samtec; ManufacturerPN: TSW-102-07-T-S; Part_Type: CON/HEADER; SiLabsPN: TSW-102-07-T-S; Silk: IN8/SDA; Type: Unshrouded; Datasheet: TSW_TH.pdf
R46 R49 R63 R64 = RES_V: RES, 1.02K, 1/16W, ±0.1%, ThinFilm, 0402; Manufacturer: Venkel; ManufacturerPN: TFCR0402-16W-E-1021B; Part_Type: RES/SMT; Rating: 1/16W; SiLabsPN: TFCR0402-16W-E-1021B; Tolerance: ±0.1%; Type: ThickFilm; Datasheet: PID_TFCR.pdf
R52-R55 = RES_V: RES, 2K, 1/16W, ±1%, ThickFilm, 0402; Manufacturer: Venkel; ManufacturerPN: CR0402-16W-2001F; Part_Type: RES/SMT; Rating: 1/16W; SiLabsPN: CR0402-16W-2001F; Tolerance: ±1%; Type: ThickFilm; Datasheet: PID_CR.pdf
R66 = RES_V: RES, 412, 1/16W, ±25PPM, ±0.1%, ThinFilm, 0402; Manufacturer: Venkel; ManufacturerPN: TFCR0402-16W-E-4120B; Part_Type: RES/SMT; Rating: 1/16W; SiLabsPN: TFCR0402-16W-E-4120B; Tolerance: ±0.1%; Type: ThinFilm; Datasheet: PID_TFCR.pdf
R67-R69 = RES_V: RES, 220 Ohm, 1/16W, ±5%, ThickFilm, 0402; Manufacturer: Venkel; ManufacturerPN: CR0402-16W-221J; Part_Type: RES/SMT; Rating: 1/16W; SiLabsPN: CR0402-16W-221J; Tolerance: ±5%; Type: ThickFilm; Datasheet: PID_CR.pdf
R97 R100 R102 R104 = RES_V: RES, 825 Ohm, 1/10W, ±1%, ThickFilm, 0603; Manufacturer: Venkel; ManufacturerPN: CR0603-10W-8250F; Part_Type: RES/SMT; Rating: 1/10W; SiLabsPN: CR0603-10W-8250F; Tolerance: ±1%; Type: ThickFilm; Datasheet: PID_CR.pdf
R98 R99 R101 R103 = RES_V: RES, 511 Ohm, 1/10W, ±1%, ThickFilm, 0603; Manufacturer: Venkel; ManufacturerPN: CR0603-10W-5110F; Part_Type: RES/SMT; Rating: 1/10W; SiLabsPN: CR0603-10W-5110F; Tolerance: ±1%; Type: ThickFilm; Datasheet: PID_CR.pdf
S1 = SW_PUSHBUTTON: 6mmx6mm push button sw Normal open; Manufacturer: Mountain Switch; ManufacturerPN: 101-0161-EV; Part_Type: SWITCH; Rating: 50mA; SiLabsPN: 101-0161-EV; Silk: RESET; Voltage: 12Vdc; Datasheet: MS-100596.pdf
TP3 = TEST_POINT: TH Red TESTPOINT; Manufacturer: Kobiconn; ManufacturerPN: 151-207; SiLabsPN: 151-207; Silk: SDA; Type: Red
TP4 = TEST_POINT: TH Red TESTPOINT; Manufacturer: Kobiconn; ManufacturerPN: 151-207; SiLabsPN: 151-207; Silk: SCL; Type: Red
TP11 TP14-TP17 = TEST_POINT: TH Red TESTPOINT; Manufacturer: Kobiconn; ManufacturerPN: 151-207; SiLabsPN: 151-207; Silk: GND; Type: Red
U3 U5 U10 U11 = NLSV1T244: Buffer(single) non inverting with tristate and level translation; Manufacturer: On Semi; ManufacturerPN: NLSV1T244MUTBG; Part_Type: IC; SiLabsPN: NLSV1T244MUTBG; Type: Single; Voltage: .9-4.5V; Datasheet: NLSV1T244.pdf
U4 = VREF-3PIN: Micropower, Precision Series Mode Voltage Reference; Manufacturer: Analog Devices; ManufacturerPN: AD1582BRT; Part_Type: IC; SiLabsPN: AD1582BRT; Type: VREF; Datasheet: AD1582.PDF
U6 = PCA9517A: I2C buffer, Level translating I2C-bus repeater; Manufacturer: NXP; ManufacturerPN: PCA9517AD; Part_Type: IC; SiLabsPN: PCA9517AD; Datasheet: PCA9517A_2.pdf
U8 = C8051F340: IC 8051 MCU FLASH 64K 48TQFP; Manufacturer: SiLabs; ManufacturerPN: C8051F340-GQ; Part_Type: IC/SILABS; SiLabsPN: C8051F340-GQ; Type: MCU; Voltage: 5.5V; Datasheet: C8051F34x.pdf
U13 U14 = ADG728: CMOS, Low-Voltage, 2-Wire Serially-Controlled, Matrix Switch; Manufacturer: Analog Devices; ManufacturerPN: ADG728BRUZ; Part_Type: IC; SiLabsPN: ADG728BRUZ; Voltage: 2.7-5.5V; Datasheet: ADG728.pdf
C60 = CAP_NP_9: CAP, 1uF, 10V, ±10%, X7R, 0603; Manufacturer: Venkel; ManufacturerPN: C0603X7R100-105K; Part_Type: CAP/NP; SiLabsPN: C0603X7R100-105K; Tolerance: ±10%; Type: X7R; Voltage: 10V; Datasheet: PID_C.pdf
C62 = CAP_NP_6: CAP, 1uF, 10V, ±10%, X7R, 0603; Manufacturer: Venkel; ManufacturerPN: C0603X7R100-105K; Part_Type: CAP/NP; SiLabsPN: C0603X7R100-105K; Tolerance: ±10%; Type: X7R; Voltage: 10V; Datasheet: PID_C.pdf
C64 = CAP_NP_7: CAP, 1uF, 10V, ±10%, X7R, 0603; Manufacturer: Venkel; ManufacturerPN: C0603X7R100-105K; Part_Type: CAP/NP; SiLabsPN: C0603X7R100-105K; Tolerance: ±10%; Type: X7R; Voltage: 10V; Datasheet: PID_C.pdf
C66 = CAP_NP_2: CAP, 1uF, 10V, ±10%, X7R, 0603; Manufacturer: Venkel; ManufacturerPN: C0603X7R100-105K; Part_Type: CAP/NP; SiLabsPN: C0603X7R100-105K; Tolerance: ±10%; Type: X7R; Voltage: 10V; Datasheet: PID_C.pdf
C68 = CAP_NP_13: CAP, 1uF, 10V, ±10%, X7R, 0603; Manufacturer: Venkel; ManufacturerPN: C0603X7R100-105K; Part_Type: CAP/NP; SiLabsPN: C0603X7R100-105K; Tolerance: ±10%; Type: X7R; Voltage: 10V; Datasheet: PID_C.pdf
C69 = CAP_NP_3: CAP, 1uF, 10V, ±10%, X7R, 0603; Manufacturer: Venkel; ManufacturerPN: C0603X7R100-105K; Part_Type: CAP/NP; SiLabsPN: C0603X7R100-105K; Tolerance: ±10%; Type: X7R; Voltage: 10V; Datasheet: PID_C.pdf
C70 = CAP_NP_23: CAP, 1uF, 10V, ±10%, X7R, 0603; Manufacturer: Venkel; ManufacturerPN: C0603X7R100-105K; Part_Type: CAP/NP; SiLabsPN: C0603X7R100-105K; Tolerance: ±10%; Type: X7R; Voltage: 10V; Datasheet: PID_C.pdf
C72 = CAP_NP_16: CAP, 0.01uF, 10V, ±20%, X7R, 0402; Manufacturer: Venkel; ManufacturerPN: C0402X7R100-103M; Part_Type: CAP/NP; SiLabsPN: C0402X7R100-103M; Tolerance: ±20%; Type: X7R; Voltage: 10V; Datasheet: PID_C.pdf
C73 = CAP_NP_8: CAP, 1uF, 10V, ±10%, X7R, 0603; Manufacturer: Venkel; ManufacturerPN: C0603X7R100-105K; Part_Type: CAP/NP; SiLabsPN: C0603X7R100-105K; Tolerance: ±10%; Type: X7R; Voltage: 10V; Datasheet: PID_C.pdf
C75 = CAP_NP_4: CAP, 0.01uF, 10V, ±20%, X7R, 0402; Manufacturer: Venkel; ManufacturerPN: C0402X7R100-103M; Part_Type: CAP/NP; SiLabsPN: C0402X7R100-103M; Tolerance: ±20%; Type: X7R; Voltage: 10V; Datasheet: PID_C.pdf
C77 = CAP_NP_24: CAP, 0.1uF, 10V, ±10%, X7R, 0402; Manufacturer: Venkel; ManufacturerPN: C0402X7R100-104K; Part_Type: CAP/NP; SiLabsPN: C0402X7R100-104K; Tolerance: ±10%; Type: X7R; Voltage: 10V; Datasheet: PID_C.pdf
C78 = CAP_NP_15: CAP, 1uF, 10V, ±10%, X7R, 0603; Manufacturer: Venkel; ManufacturerPN: C0603X7R100-105K; Part_Type: CAP/NP; SiLabsPN: C0603X7R100-105K; Tolerance: ±10%; Type: X7R; Voltage: 10V; Datasheet: PID_C.pdf
C80 = CAP_NP_11: CAP, 1uF, 10V, ±10%, X7R, 0603; Manufacturer: Venkel; ManufacturerPN: C0603X7R100-105K; Part_Type: CAP/NP; SiLabsPN: C0603X7R100-105K; Tolerance: ±10%; Type: X7R; Voltage: 10V; Datasheet: PID_C.pdf
C81 = CAP_NP_10: CAP, 1uF, 10V, ±10%, X7R, 0603; Manufacturer: Venkel; ManufacturerPN: C0603X7R100-105K; Part_Type: CAP/NP; SiLabsPN: C0603X7R100-105K; Tolerance: ±10%; Type: X7R; Voltage: 10V; Datasheet: PID_C.pdf
C83 = CAP_NP_1: CAP, 0.01uF, 10V, ±20%, X7R, 0402; Manufacturer: Venkel; ManufacturerPN: C0402X7R100-103M; Part_Type: CAP/NP; SiLabsPN: C0402X7R100-103M; Tolerance: ±20%; Type: X7R; Voltage: 10V; Datasheet: PID_C.pdf
C85 = CAP_NP_19: CAP, 1uF, 10V, ±10%, X7R, 0603; Manufacturer: Venkel; ManufacturerPN: C0603X7R100-105K; Part_Type: CAP/NP; SiLabsPN: C0603X7R100-105K; Tolerance: ±10%; Type: X7R; Voltage: 10V; Datasheet: PID_C.pdf
C86 = CAP_NP_20: CAP, 0.01uF, 10V, ±20%, X7R, 0402; Manufacturer: Venkel; ManufacturerPN: C0402X7R100-103M; Part_Type: CAP/NP; SiLabsPN: C0402X7R100-103M; Tolerance: ±20%; Type: X7R; Voltage: 10V; Datasheet: PID_C.pdf
C88 = CAP_NP_14: CAP, 1uF, 10V, ±10%, X7R, 0603; Manufacturer: Venkel; ManufacturerPN: C0603X7R100-105K; Part_Type: CAP/NP; SiLabsPN: C0603X7R100-105K; Tolerance: ±10%; Type: X7R; Voltage: 10V; Datasheet: PID_C.pdf
C89 = CAP_NP_12: CAP, 1uF, 10V, ±10%, X7R, 0603; Manufacturer: Venkel; ManufacturerPN: C0603X7R100-105K; Part_Type: CAP/NP; SiLabsPN: C0603X7R100-105K; Tolerance: ±10%; Type: X7R; Voltage: 10V; Datasheet: PID_C.pdf
C90 = CAP_NP_17: CAP, 1uF, 10V, ±10%, X7R, 0603; Manufacturer: Venkel; ManufacturerPN: C0603X7R100-105K; Part_Type: CAP/NP; SiLabsPN: C0603X7R100-105K; Tolerance: ±10%; Type: X7R; Voltage: 10V; Datasheet: PID_C.pdf
C91 = CAP_NP_5: CAP, 1uF, 10V, ±10%, X7R, 0603; Manufacturer: Venkel; ManufacturerPN: C0603X7R100-105K; Part_Type: CAP/NP; SiLabsPN: C0603X7R100-105K; Tolerance: ±10%; Type: X7R; Voltage: 10V; Datasheet: PID_C.pdf
C92 = CAP_NP_25: CAP, 1uF, 10V, ±10%, X7R, 0603; Manufacturer: Venkel; ManufacturerPN: C0603X7R100-105K; Part_Type: CAP/NP; SiLabsPN: C0603X7R100-105K; Tolerance: ±10%; Type: X7R; Voltage: 10V; Datasheet: PID_C.pdf
J26-J30 = JUMPER: 2x1, 0.1in pitch, Tin Plated; Manufacturer: Samtec; ManufacturerPN: TSW-102-07-T-S; Part_Type: CON/HEADER; SiLabsPN: TSW-102-07-T-S; Type: Unshrouded; Datasheet: TSW_TH.pdf
R70-R73 = RES_V: RES, 10K, 1/16W, ±5%, ThickFilm, 0402; Manufacturer: Venkel; ManufacturerPN: CR0402-16W-103J; Part_Type: RES/SMT; Rating: 1/16W; SiLabsPN: CR0402-16W-103J; Tolerance: ±5%; Type: ThickFilm; Datasheet: PID_CR.pdf
R74 = RES_V: RES, 47.5K, 1/10W, ±1%, ThickFilm, 0603; Manufacturer: Venkel; ManufacturerPN: CR0603-10W-4752F; Part_Type: RES/SMT; Rating: 1/10W; SiLabsPN: CR0603-10W-4752F; Tolerance: ±1%; Type: ThickFilm; Datasheet: PID_CR.pdf
R75 = RES_V: RES, 15.4K, 1/10W, ±1%, ThickFilm, 0603; Manufacturer: Venkel; ManufacturerPN: CR0603-10W-1542F; Part_Type: RES/SMT; Rating: 1/10W; SiLabsPN: CR0603-10W-1542F; Tolerance: ±1%; Type: ThickFilm; Datasheet: PID_CR.pdf
R105-R109 = RES_V: RES, 10 Ohm, 2W, ±0.5%, ThickFilm, 1206; Manufacturer: Venkel; ManufacturerPN: CR2512-2W-10R0D; Part_Type: RES/SMT; Rating: 2 W; SiLabsPN: CR2512-2W-10R0D; Tolerance: ±0.5%; Type: ThickFilm; Datasheet: PID_CR.pdf
TP5 = TEST_POINT: TH Red TESTPOINT; Manufacturer: Kobiconn; ManufacturerPN: 151-207; SiLabsPN: 151-207; Silk: VDDO0; Type: Red
TP6 = TEST_POINT: TH Red TESTPOINT; Manufacturer: Kobiconn; ManufacturerPN: 151-207; SiLabsPN: 151-207; Silk: VDDO1; Type: Red
TP7 = TEST_POINT: TH Red TESTPOINT; Manufacturer: Kobiconn; ManufacturerPN: 151-207; SiLabsPN: 151-207; Silk: VDDO2; Type: Red
TP8 = TEST_POINT: TH Red TESTPOINT; Manufacturer: Kobiconn; ManufacturerPN: 151-207; SiLabsPN: 151-207; Silk: VDDO3; Type: Red
TP10 = TEST_POINT: TH Red TESTPOINT; Manufacturer: Kobiconn; ManufacturerPN: 151-207; SiLabsPN: 151-207; Silk: +3.3V; Type: Red
TP13 = TEST_POINT: TH Red TESTPOINT; Manufacturer: Kobiconn; ManufacturerPN: 151-207; SiLabsPN: 151-207; Silk: VDD; Type: Red
U15-U18 U22 = MAX8869: LOW DROP ADJUSTABLE POSITIVE VOLTAGE REGULATOR, .8-5V; Manufacturer: MAXIM; ManufacturerPN: MAX8869EUE50; Part_Type: IC/VREG/LIN; Rating: 1A; SiLabsPN: MAX8869EUE50; Datasheet: MAX8869.PDF
U19 U20 U23 = AD5263: Quad, 15V, 256-Position, Digital Pot with Pin-Selectable SPI/I2C / Quad, 15 V, 256-Position, Digital Potentiometer with Pin-Selectable SPI/I2C; Manufacturer: Analog Devices; ManufacturerPN: AD5263BRUZ20; Part_Type: IC; SiLabsPN: AD5263BRUZ20; Datasheet: AD5263.pdf
U21 = MAX8869: LOW DROP ADJUSTABLE POSITIVE VOLTAGE REGULATOR, .8-5V; Manufacturer: Maxim; ManufacturerPN: MAX8869EUE50; Part_Type: IC/VREG/LIN; Rating: 1A; SiLabsPN: MAX8869EUE50; Datasheet: MAX8869.PDF

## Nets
+3.3V: C31.1 C33.1 C35.1 C39.1 C42.1 C46.1 C49.1 C81.1 C82.1 C86.2 J23.1 R7.2 R52.1 R53.1 R54.1 R55.1 R60.1 R65.1 R67.1 R68.1 R69.1 R74.2 R96.2 R97.2 R100.2 R102.2 R104.2 TP10.1(Point) U3.1(VCCA) U4.3(VIN) U5.1(VCCA) U6.1(VCCA) U8.10(VDD) U8.11(REGIN) U10.1(VCCA) U11.1(VCCA) U13.11(S6) U22.12(OUT) U22.13(OUT) U22.14(OUT) U22.15(OUT)
+5V_USB: C38.1 C43.2 C48.1 C51.1 C55.1 C56.1 C57.1 C68.1 C69.1 C70.1 C73.1 C74.1 C77.1 C80.1 C84.1 C85.1 D1.K(CATHODE) D2.K(CATHODE) J21.1 R50.1 R51.1 R66.2 R70.2 R71.2 R72.2 R73.1 R76.1 U6.8(VCCB) U8.12(VBUS) U13.2(RESETB) U13.13(VDD) U14.2(RESETB) U14.13(VDD) U14.16(A0) U15.2(IN) U15.3(IN) U15.4(IN) U15.5(IN) U16.2(IN) U16.3(IN) U16.4(IN) U16.5(IN) U17.2(IN) U17.3(IN) U17.4(IN) U17.5(IN) U18.2(IN) U18.3(IN) U18.4(IN) U18.5(IN) U19.7(VDD) U19.9(DIS) U19.10(VLOGIC) U20.7(VDD) U20.9(DIS) U20.10(VLOGIC) U20.13(CSB/AD0) U21.2(IN) U21.3(IN) U21.4(IN) U21.5(IN) U22.2(IN) U22.3(IN) U22.4(IN) U22.5(IN) U23.7(VDD) U23.9(DIS) U23.10(VLOGIC) U23.14(RESB/AD1)
GND: C4.2 C5.2 C7.2 C8.2 C9.2 C11.2 C12.2 C13.2 C14.2 C18.2 C20.2 C22.2 C23.2 C24.2 C28.2 C30.2 C31.2 C32.2 C33.2 C34.2 C35.2 C36.2 C37.2 C38.2 C39.2 C42.2 C43.1 C46.2 C47.2 C48.2 C49.2 C50.2 C51.2 C52.2 C55.2 C56.2 C57.2 C58.2 C59.2 C60.2 C61.2 C62.2 C63.2 C64.2 C65.2 C66.2 C67.2 C68.2 C69.2 C70.2 C73.2 C74.2 C77.2 C78.2 C79.2 C80.2 C81.2 C82.2 C84.2 C85.2 C87.2 C88.2 C89.2 C90.2 C91.2 C92.2 C93.2 D1.A(ANODE) D2.A(ANODE) J1.2(SHIELD) J1.3(SHIELD) J1.4(SHIELD) J1.5(SHIELD) J2.2(SHIELD) J2.3(SHIELD) J2.4(SHIELD) J2.5(SHIELD) J3.2(SHIELD) J3.3(SHIELD) J3.4(SHIELD) J3.5(SHIELD) J4.2(SHIELD) J4.3(SHIELD) J4.4(SHIELD) J4.5(SHIELD) J5.2(SHIELD) J5.3(SHIELD) J5.4(SHIELD) J5.5(SHIELD) J6.2(SHIELD) J6.3(SHIELD) J6.4(SHIELD) J6.5(SHIELD) J7.2(SHIELD) J7.3(SHIELD) J7.4(SHIELD) J7.5(SHIELD) J8.2(SHIELD) J8.3(SHIELD) J8.4(SHIELD) J8.5(SHIELD) J9.2(SHIELD) J9.3(SHIELD) J9.4(SHIELD) J9.5(SHIELD) J10.2(SHIELD) J10.3(SHIELD) J10.4(SHIELD) J10.5(SHIELD) J11.2(SHIELD) J11.3(SHIELD) J11.4(SHIELD) J11.5(SHIELD) J12.2(SHIELD) J12.3(SHIELD) J12.4(SHIELD) J12.5(SHIELD) J13.2(SHIELD) J13.3(SHIELD) J13.4(SHIELD) J13.5(SHIELD) J14.2(SHIELD) J14.3(SHIELD) J14.4(SHIELD) J14.5(SHIELD) J21.4 J21.5 J21.6 J23.2 J23.3 J23.9 R3.1 R6.1 R11.1 R16.1 R27.1 R34.1 R35.1 R36.1 R40.1 R43.1 R47.2 R49.1 R64.2 R75.2 R95.2 R98.2 R99.2 R101.2 R103.2 R110.1 R111.1 R115.2 R116.2 R117.2 R118.2 R119.2 R120.2 S1.1 S1.2 TP11.1(Point) TP14.1(Point) TP15.1(Point) TP16.1(Point) TP17.1(Point) U1.2(GND) U1.4(GND) U2.23(GND) U2.25(GND) U3.3(GND) U4.2(GND) U5.3(GND) U6.4(GND) U7.1(XTAL1) U7.3(XTAL2) U8.7(GND) U8.17(P4.5) U8.44(P1.2) U8.46(P1.0) U10.3(GND) U11.3(GND) U13.14(GND) U13.15(A1) U13.16(A0) U14.14(GND) U14.15(A1) U15.10(GND) U15.17(EPAD) U16.10(GND) U16.17(EPAD) U17.10(GND) U17.17(EPAD) U18.10(GND) U18.17(EPAD) U19.5(A3) U19.8(GND) U19.13(CSB/AD0) U19.14(RESB/AD1) U19.18(VSS) U19.20(A4) U20.5(A3) U20.8(GND) U20.14(RESB/AD1) U20.18(VSS) U20.20(A4) U21.10(GND) U21.17(EPAD) U22.10(GND) U22.17(EPAD) U23.5(A3) U23.8(GND) U23.13(CSB/AD0) U23.18(VSS) U23.20(A4)
VDD: C79.1 J30.2 R83.1 R84.1 TP13.1(Point) U13.12(S5)
VDD_int_en: U21.7(SHDNB) U23.16(SDO/O1)
VDD_pin: C83.2 C92.1 R109.1 U14.12(S5) U21.12(OUT) U21.13(OUT) U21.14(OUT) U21.15(OUT)
VDDO0: C61.1 J26.2 R2.2 R5.2 R80.1 TP5.1(Point) U13.4(S1)
VDDO0_int_en: U15.7(SHDNB) U19.16(SDO/O1)
VDDO0_pin: C71.2 C88.1 R105.1 U14.4(S1) U15.12(OUT) U15.13(OUT) U15.14(OUT) U15.15(OUT)
VDDO1: C63.1 J27.2 R9.2 R15.2 R79.1 TP6.1(Point) U13.5(S2)
VDDO1_int_en: U16.7(SHDNB) U19.17(NC/O2)
VDDO1_pin: C72.2 C89.1 R106.1 U14.5(S2) U16.12(OUT) U16.13(OUT) U16.14(OUT) U16.15(OUT)
VDDO2: C65.1 J28.2 R20.2 R33.2 R81.1 TP7.1(Point) U13.6(S3)
VDDO2_int_en: U18.7(SHDNB) U20.16(SDO/O1)
VDDO2_pin: C76.2 C90.1 R107.1 U14.6(S3) U18.12(OUT) U18.13(OUT) U18.14(OUT) U18.15(OUT)
VDDO3: C67.1 J29.2 R38.2 R42.2 R82.1 TP8.1(Point) U13.7(S4)
VDDO3_int_en: U17.7(SHDNB) U20.17(NC/O2)
VDDO3_pin: C75.2 C91.1 R108.1 U14.7(S4) U17.12(OUT) U17.13(OUT) U17.14(OUT) U17.15(OUT)
I2C_5V_EN: R76.2 U6.5(EN) U8.28(P3.2)
IN1_DRIVE: U3.2(A) U8.43(P1.3)
IN1_DRV: J15.2 R22.2
IN1_EN: U3.4(OEB) U8.29(P3.1)
IN2_DRIVE: U5.2(A) U8.39(P1.7)
IN2_DRV: J16.2 R21.2
IN2_EN: U5.4(OEB) U8.27(P3.3)
IN3_DRIVE: J17.1 U8.38(P2.0)
IN3_DRV: J17.2 R24.2
IN4_DRIVE: J18.1 U8.37(P2.1)
IN4_DRV: J18.2 R23.2
IN5_DRIVE: U8.36(P2.2) U10.2(A)
IN5_DRV: J20.2 R26.2
IN5_EN: U8.26(P3.4) U10.4(OEB)
IN6_DRIVE: U8.35(P2.3) U11.2(A)
IN6_DRV: J22.2 R25.2
IN6_EN: U8.25(P3.5) U11.4(OEB)
INTRPT: R7.1 TP12.1(Point) U2.8(INTR) U8.48(P0.6)
SCL_5V: R51.2 U6.7(SCLB) U13.1(SCL) U14.1(SCL) U19.12(CLK/SCL) U20.12(CLK/SCL) U23.12(CLK/SCL)
SCL_5338: J19.4 R29.1 R55.2 U2.12(IN7/SCL)
SCL_5338_DRV: J24.1 U8.34(P2.4)
SCL_DRV: J24.2 R29.2
SDA_5V: R50.2 U6.6(SDAB) U13.3(SDA) U14.3(SDA) U19.11(SDI/SDA) U20.11(SDI/SDA) U23.11(SDI/SDA)
SDA_5338: J19.2 R28.1 R52.2 U2.19(IN8/SDA)
SDA_5338_DRV: J25.1 U8.33(P2.5)
SDA_DRV: J25.2 R28.2
N03677: C62.1 J27.1 R106.2 U19.24(B2)
N73179: D2.C(COMMON) J21.2 U8.9(D-)
N92849: C72.1 U16.11(SET) U19.19(W4) U19.22(W2)
N114647: C76.1 U18.11(SET) U20.3(W1) U20.6(W3)
N114813: C75.1 U17.11(SET) U20.19(W4) U20.22(W2)
N114845: C66.1 J29.1 R108.2 U20.24(B2)
N230805: C11.1 R83.2 U2.24(VDD)
N258921: R18.1 R24.1 R77.2 U2.3(IN3)
N263573: C5.1 R79.2 U2.16(VDDO1)
N292940: C41.2 J6.1(CENTER)
N301034: C83.1 U21.11(SET) U23.3(W1) U23.6(W3)
N363865: J23.6 R62.1
N364054: J23.4 R62.2 U8.14(C2D)
N366159: C52.1 J23.5 R60.2 R61.1 S1.3 S1.4
N367528: J23.7 R61.2 U8.13(RST/C2CK)
N1247681: C86.1 R74.1 R75.1 U22.11(SET)
N1304225: C78.1 J30.1 R109.2 U23.1(B1)
N1345565: C71.1 U15.11(SET) U19.3(W1) U19.6(W3)
N1367692: C64.1 J28.1 R107.2 U20.1(B1)
N1589702: C32.1 R97.1 R98.1 U3.6(VCCB)
N2026942: C17.2 J4.1(CENTER)
N2027485: C15.2 J1.1(CENTER)
N2032781: C40.2 J5.1(CENTER)
N2033340: C44.2 J9.1(CENTER)
N2036564: C45.2 J10.1(CENTER)
N2639624: R73.2 U23.15(SHDN_B)
N4085334: J19.1 R54.2 TP3.1(Point) U6.3(SDAA) U8.2(P0.4)
N4217750: D3.K(CATHODE) U8.21(P4.1)
N4218698: D4.K(CATHODE) U8.20(P4.2)
N4220598: D5.K(CATHODE) U8.19(P4.3)
N4225039: D6.K(CATHODE) U8.18(P4.4)
N4284225: C37.1 R46.1 R49.2 U8.45(P1.1)
N5004248: C13.1 R84.2 U2.7(VDD)
N6019398: C26.2 J11.1(CENTER)
N6027874: C27.2 J13.1(CENTER)
N6151631: R39.1 R45.2 U2.6(IN6) U7.4(GND)
N6275139: R17.1 R23.1 R78.2 U2.4(IN4)
N7212817: C34.1 R46.2 U4.1(VOUT) U8.41(P1.5)
N7758261: D1.C(COMMON) J21.3 U8.8(D+)
N7765853: R70.1 U19.15(SHDN_B)
N7775104: R71.1 U20.15(SHDN_B)
N9227795: C15.1 R1.1 R120.1 R121.2
N9242464: C17.1 R4.1 R119.1 R122.2
N9243923: C7.1 R4.2 R5.1 R6.2
N9245515: C40.1 R8.1 R118.1 R123.2
N9247490: C41.1 R14.1 R117.1 R124.2
N9248716: C44.1 R19.1 R116.1 R125.2
N9249094: C45.1 R32.1 R115.1 R126.2
N9260371: C2.1 J2.1(CENTER)
N9301289: C3.1 J3.1(CENTER)
N9311781: C3.2 R13.1 R21.1
N9314948: J7.1(CENTER) R77.1
N9317088: J8.1(CENTER) R78.1
N9324491: C2.2 R12.1 R22.1
N9335020: R10.2 R13.2 U1.3(XTAL2) U2.2(IN2)
N9336187: R10.1 R12.2 U1.1(XTAL1) U2.1(IN1)
N9341725: C27.1 R25.1 R45.1
N9344963: C26.1 R26.1 R44.1
N9351646: R39.2 R44.2 U2.5(IN5) U7.2(GND)
N9354761: C54.2 J14.1(CENTER)
N9354765: C54.1 R41.1 R47.1 R128.2
N9410594: C8.1 R80.2 U2.20(VDDO0)
N9419795: C9.1 R81.2 U2.15(VDDO2)
N9424248: C12.1 R82.2 U2.11(VDDO3)
N9549643: C60.1 J26.1 R105.2 U19.1(B1)
N9704623: R72.1 U22.7(SHDNB)
N9791439: R111.2 U8.47(P0.7)
N9804827: C59.1 C87.1 R63.2 R64.1 U8.16(P4.6)
N9934293: J19.3 R53.2 TP4.1(Point) U6.2(SCLA) U8.1(P0.5)
N9969277: C58.1 R30.2 TP1.1(Point)
N9972352: C23.1 R18.2 R31.1 R35.2
N9972364: C93.1 R31.2 TP2.1(Point)
N10014456: C4.1 R1.2 R2.1 R3.2
N10029403: C14.1 R8.2 R9.1 R11.2
N10031117: C18.1 R14.2 R15.1 R16.2
N10034106: C20.1 R19.2 R20.1 R27.2
N10035908: C24.1 R32.2 R33.1 R36.2
N10040747: C28.1 R37.2 R38.1 R40.2
N10042633: C30.1 R41.2 R42.1 R43.2
N10115290: R66.1 U13.9(S8)
N10268622: J15.1 U3.5(B)
N10270045: C36.1 R99.1 R100.1 U5.6(VCCB)
N10270133: J16.1 U5.5(B)
N10271991: C47.1 R101.1 R102.1 U10.6(VCCB)
N10272095: J20.1 U10.5(B)
N10272725: C50.1 R103.1 R104.1 U11.6(VCCB)
N10272829: J22.1 U11.5(B)
N10532049: R85.2 R122.1 U2.21(CLK0B)
N10532522: R85.1 R121.1 U2.22(CLK0A)
N10533016: R86.2 R124.1 U2.17(CLK1B)
N10533028: R86.1 R123.1 U2.18(CLK1A)
N10533674: R87.2 R126.1 U2.13(CLK2B)
N10533682: R87.1 R125.1 U2.14(CLK2A)
N10534336: R88.2 R128.1 U2.9(CLK3B)
N10534344: R88.1 R127.1 U2.10(CLK3A)
N10550519: C53.1 R37.1 R95.1 R127.2
N10654178: C22.1 R17.2 R30.1 R34.2
N10681847: R96.1 U8.15(P4.7)
N10716826: R63.1 U13.8(D) U14.8(D)
N10824938: R110.2 U8.22(P4.0)
N11150181: C53.2 J12.1(CENTER)
N11207930: D3.A(ANODE) R65.2
N11207931: D5.A(ANODE) R68.2
N11207933: D6.A(ANODE) R69.2
N11207937: D4.A(ANODE) R67.2

Not connected (* = marked no-connect by the designer): J23 8* 10*; U8 3(P0.3)* 4(P0.2)* 5(P0.1)* 6(P0.0)* 23(P3.7) 24(P3.6) 30(P3.0)* 31(P2.7)* 32(P2.6)* 40(P1.6)* 42(P1.4)*; U13 10(S7)*; U14 9(S8)* 10(S7)* 11(S6)*; U15 1(NC)* 6(RSTB)* 8(SS)* 9(NC)* 16(NC)*; U16 1(NC)* 6(RSTB)* 8(SS)* 9(NC)* 16(NC)*; U17 1(NC)* 6(RSTB)* 8(SS)* 9(NC)* 16(NC)*; U18 1(NC)* 6(RSTB)* 8(SS)* 9(NC)* 16(NC)*; U19 2(A1)* 4(B3)* 21(B4)* 23(A2)*; U20 2(A1)* 4(B3)* 21(B4)* 23(A2)*; U21 1(NC)* 6(RSTB)* 8(SS)* 9(NC)* 16(NC)*; U22 1(NC)* 6(RSTB)* 8(SS)* 9(NC)* 16(NC)*; U23 2(A1)* 4(B3)* 17(NC/O2)* 19(W4)* 21(B4)* 22(W2)* 23(A2)* 24(B2)*

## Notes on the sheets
sheet 1
- Si5338
- Dummy XTAL used for trace matching
- Place R close to XTAL pins
- Place close to output pins
- Place the 49.9 ohm resistor and
  .1uf cap very close to the 5338
  pins. The 2K resistors can be
  further away.
sheet 2
- +1.2V
- CLKIN
- +2.5V Ref
- +1.2V
- CLKINB
- 2.7V to 5.5V
- 0.9V to 5.5V
- CMOS
- CMOSFB
- +1.2V
- FBCLK
- MCU
- +1.2V
- FBCLKB
- SCL
- SDA
- Address is 1001101
- Address is 1001100
sheet 3
- Address is 0101100
- Address is 0101101
- Voltage
- Regulators
- Address is 0101110
